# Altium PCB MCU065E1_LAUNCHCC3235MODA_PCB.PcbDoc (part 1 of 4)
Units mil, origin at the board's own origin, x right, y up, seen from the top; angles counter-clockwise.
Board outline 2300 x 4280 mil, 4 copper layers (TOP, GND, PWR, BOTTOM), stack 62 mil thick; 300 components, 199 nets, 970 pads, 475 vias.
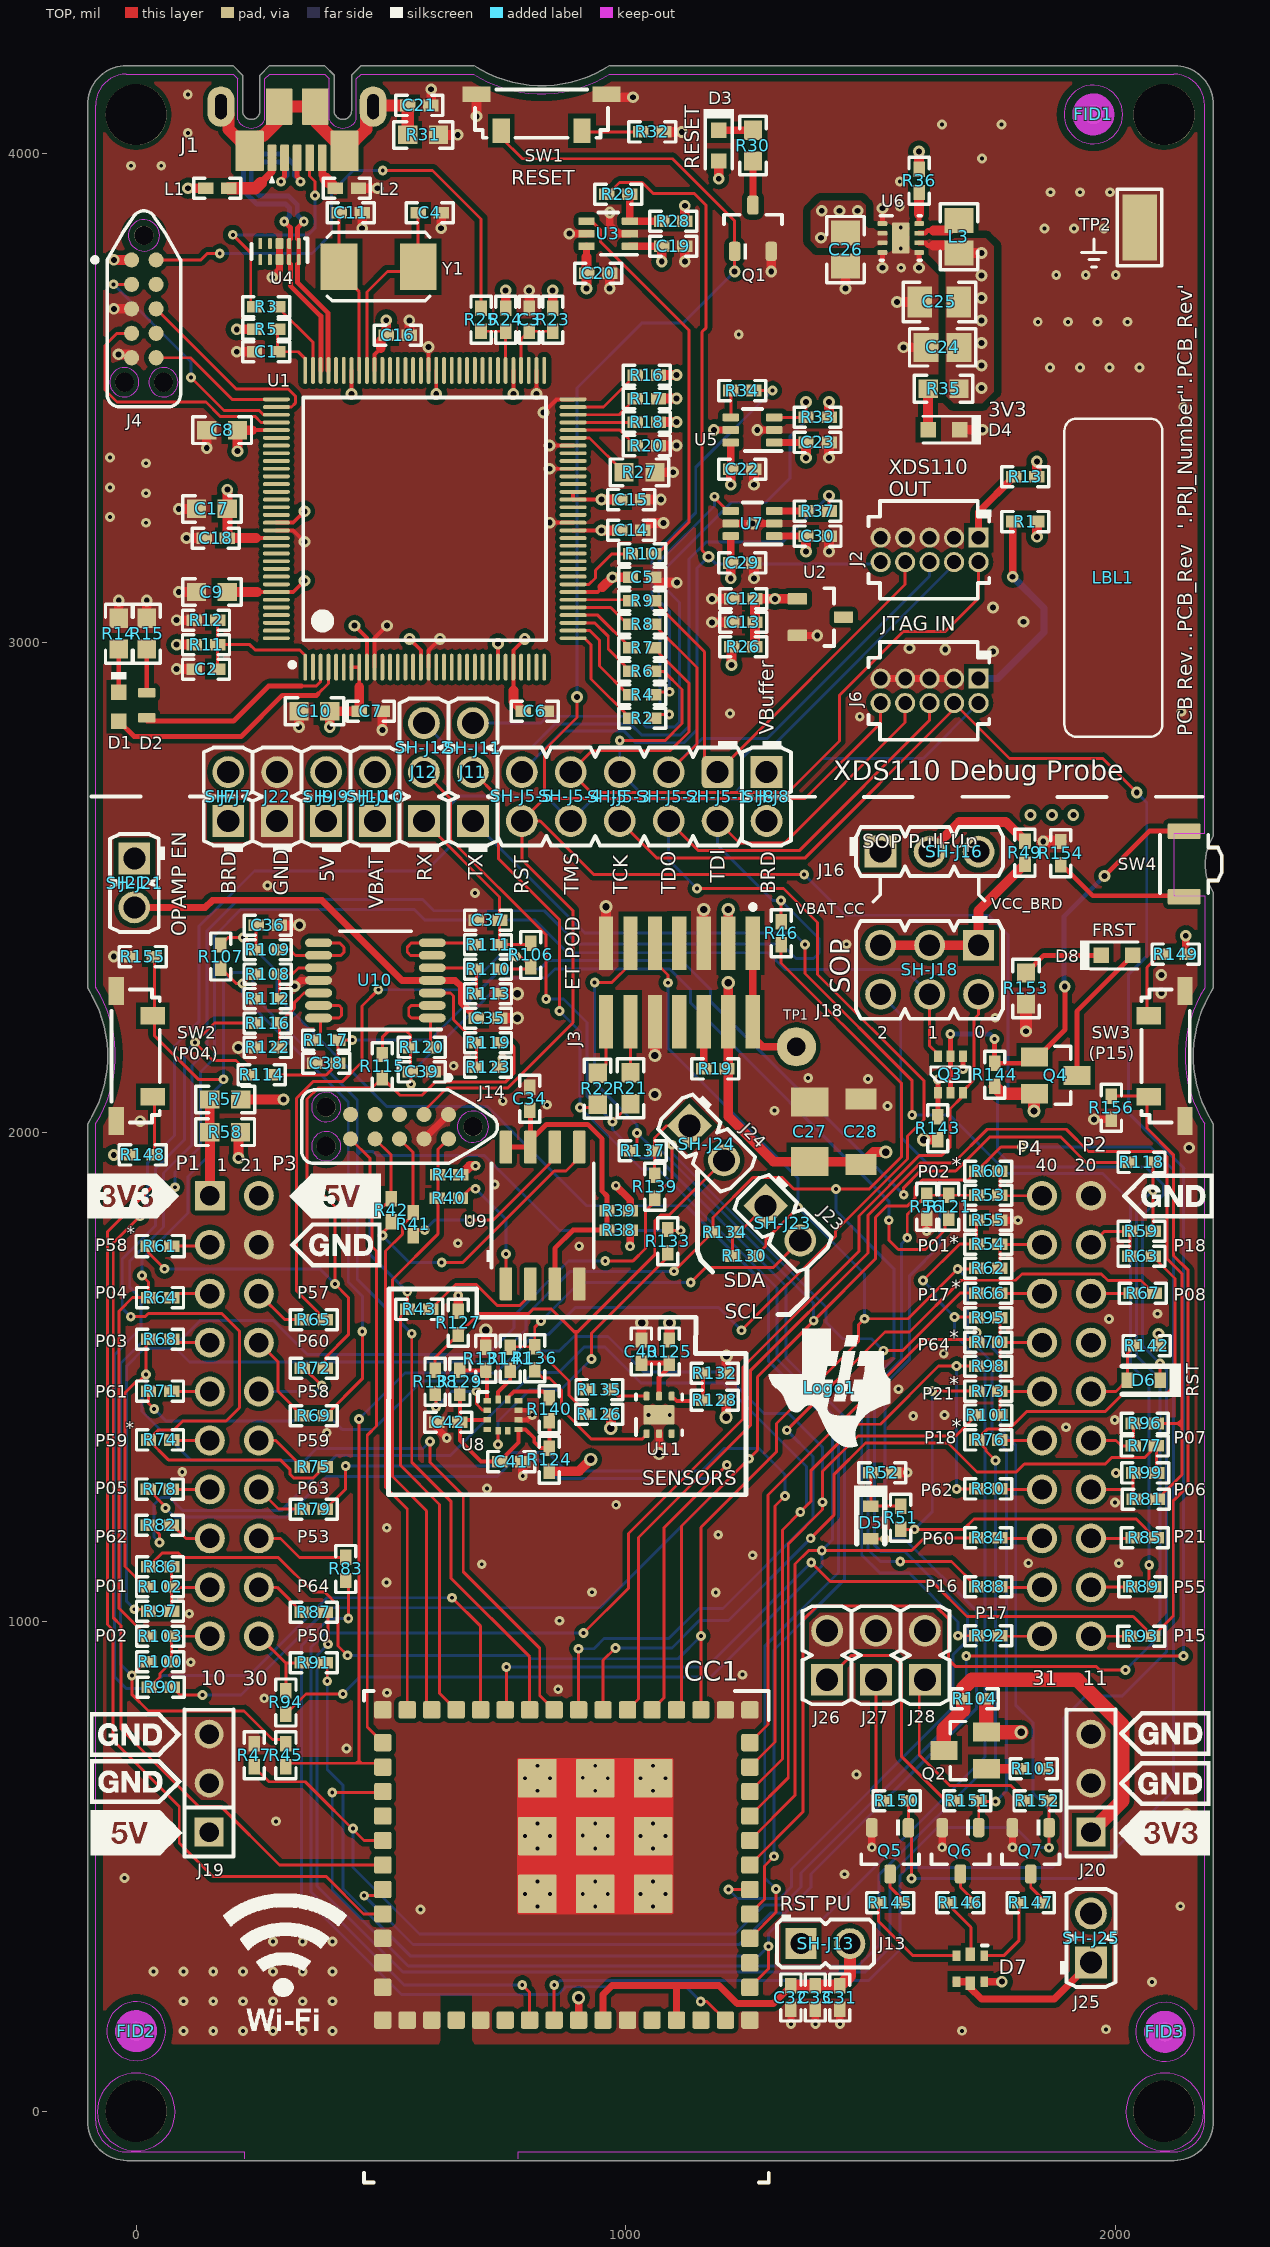
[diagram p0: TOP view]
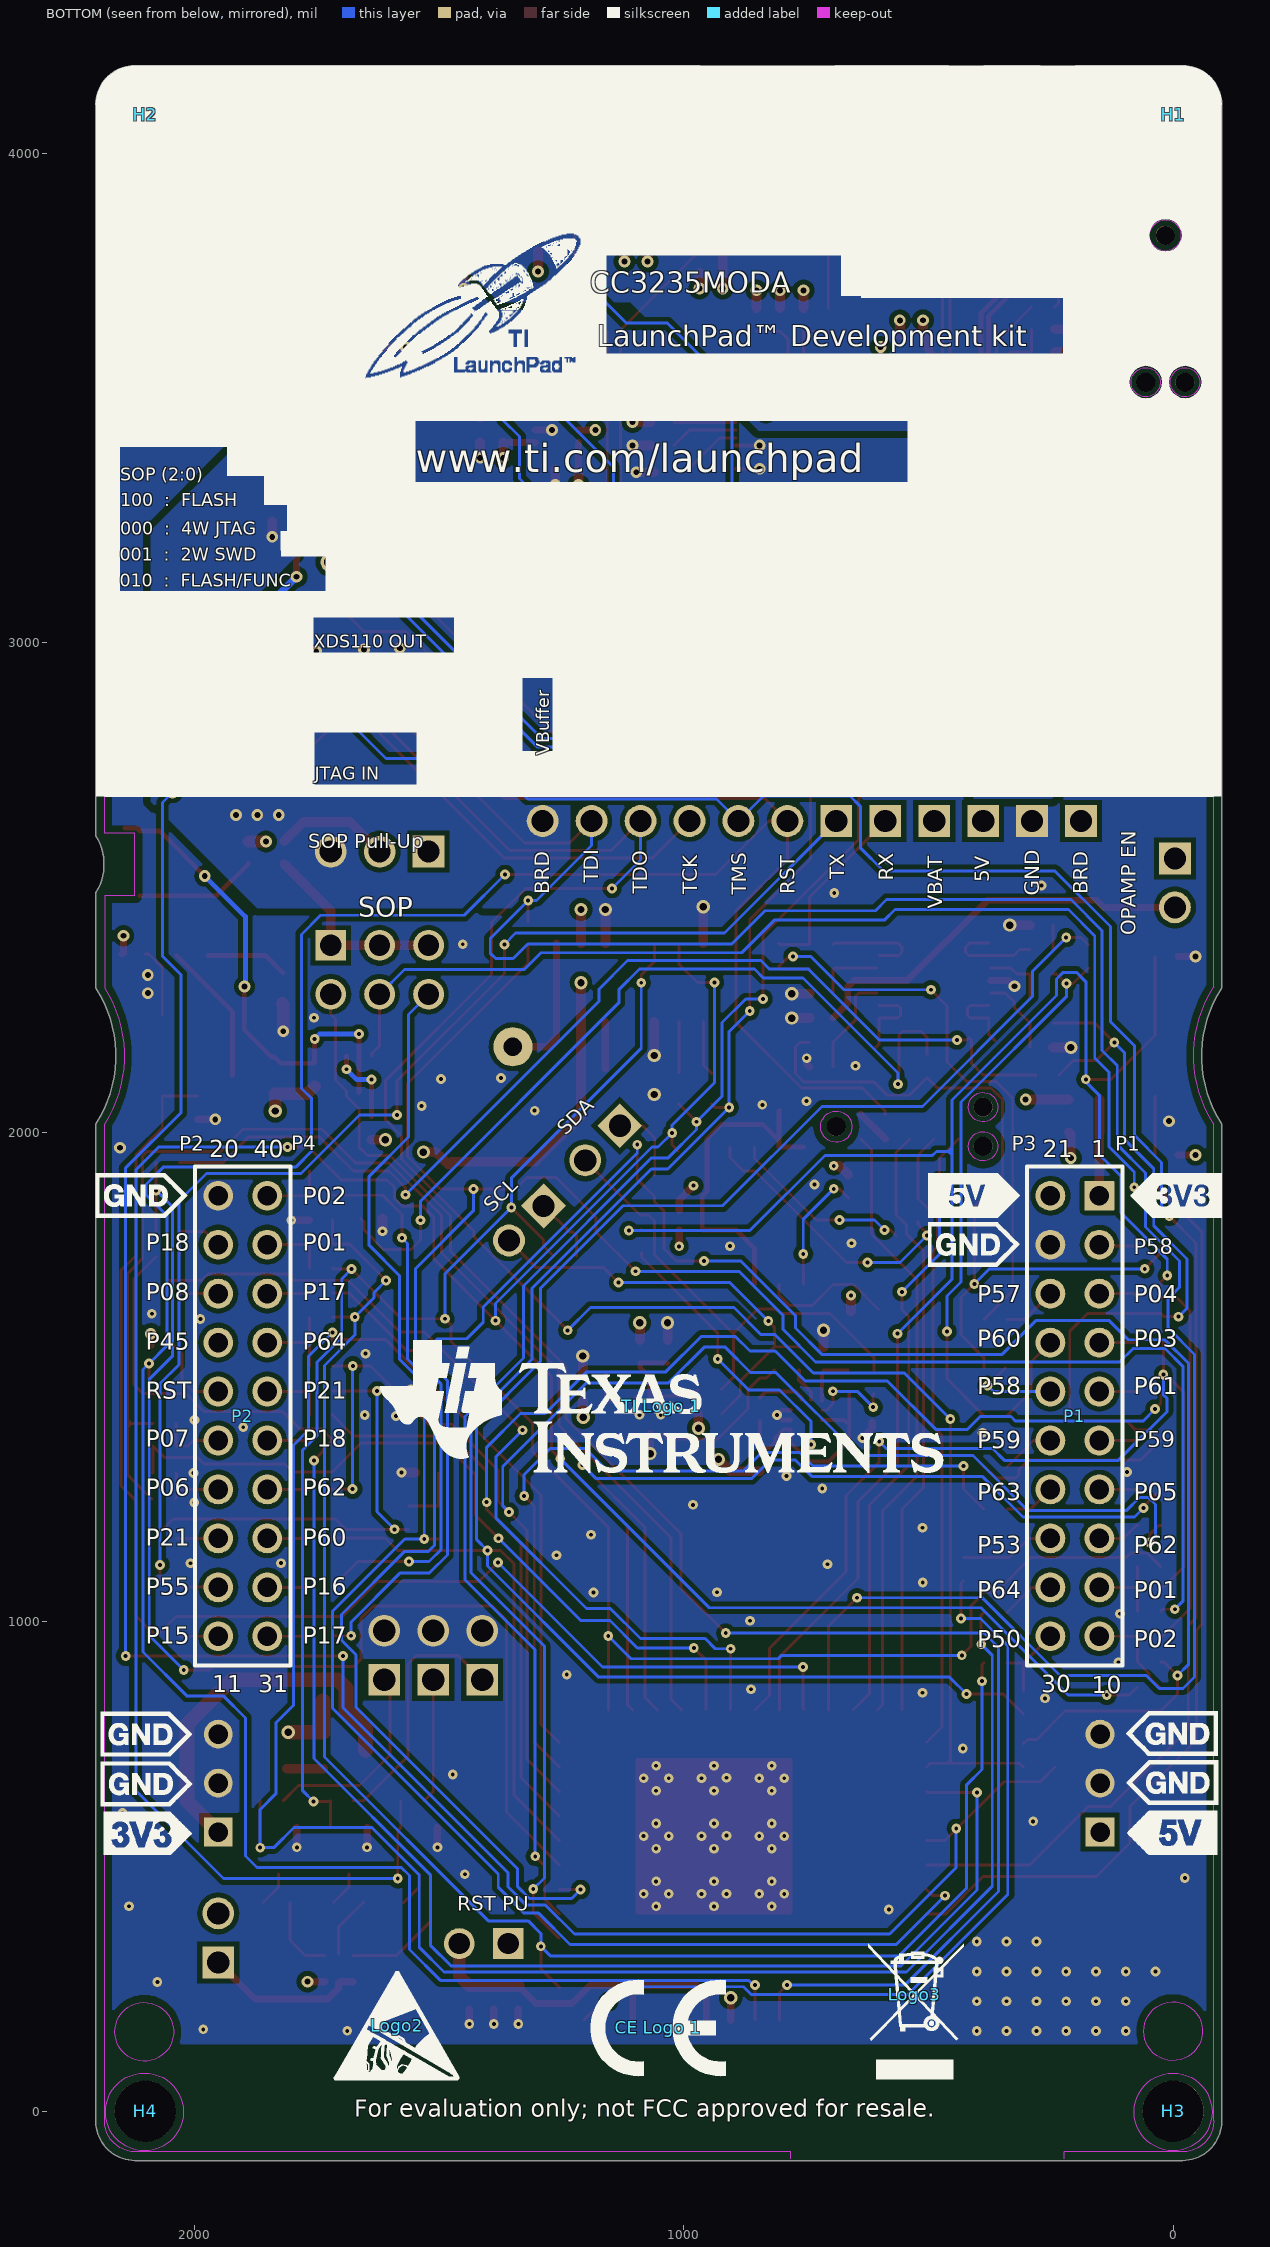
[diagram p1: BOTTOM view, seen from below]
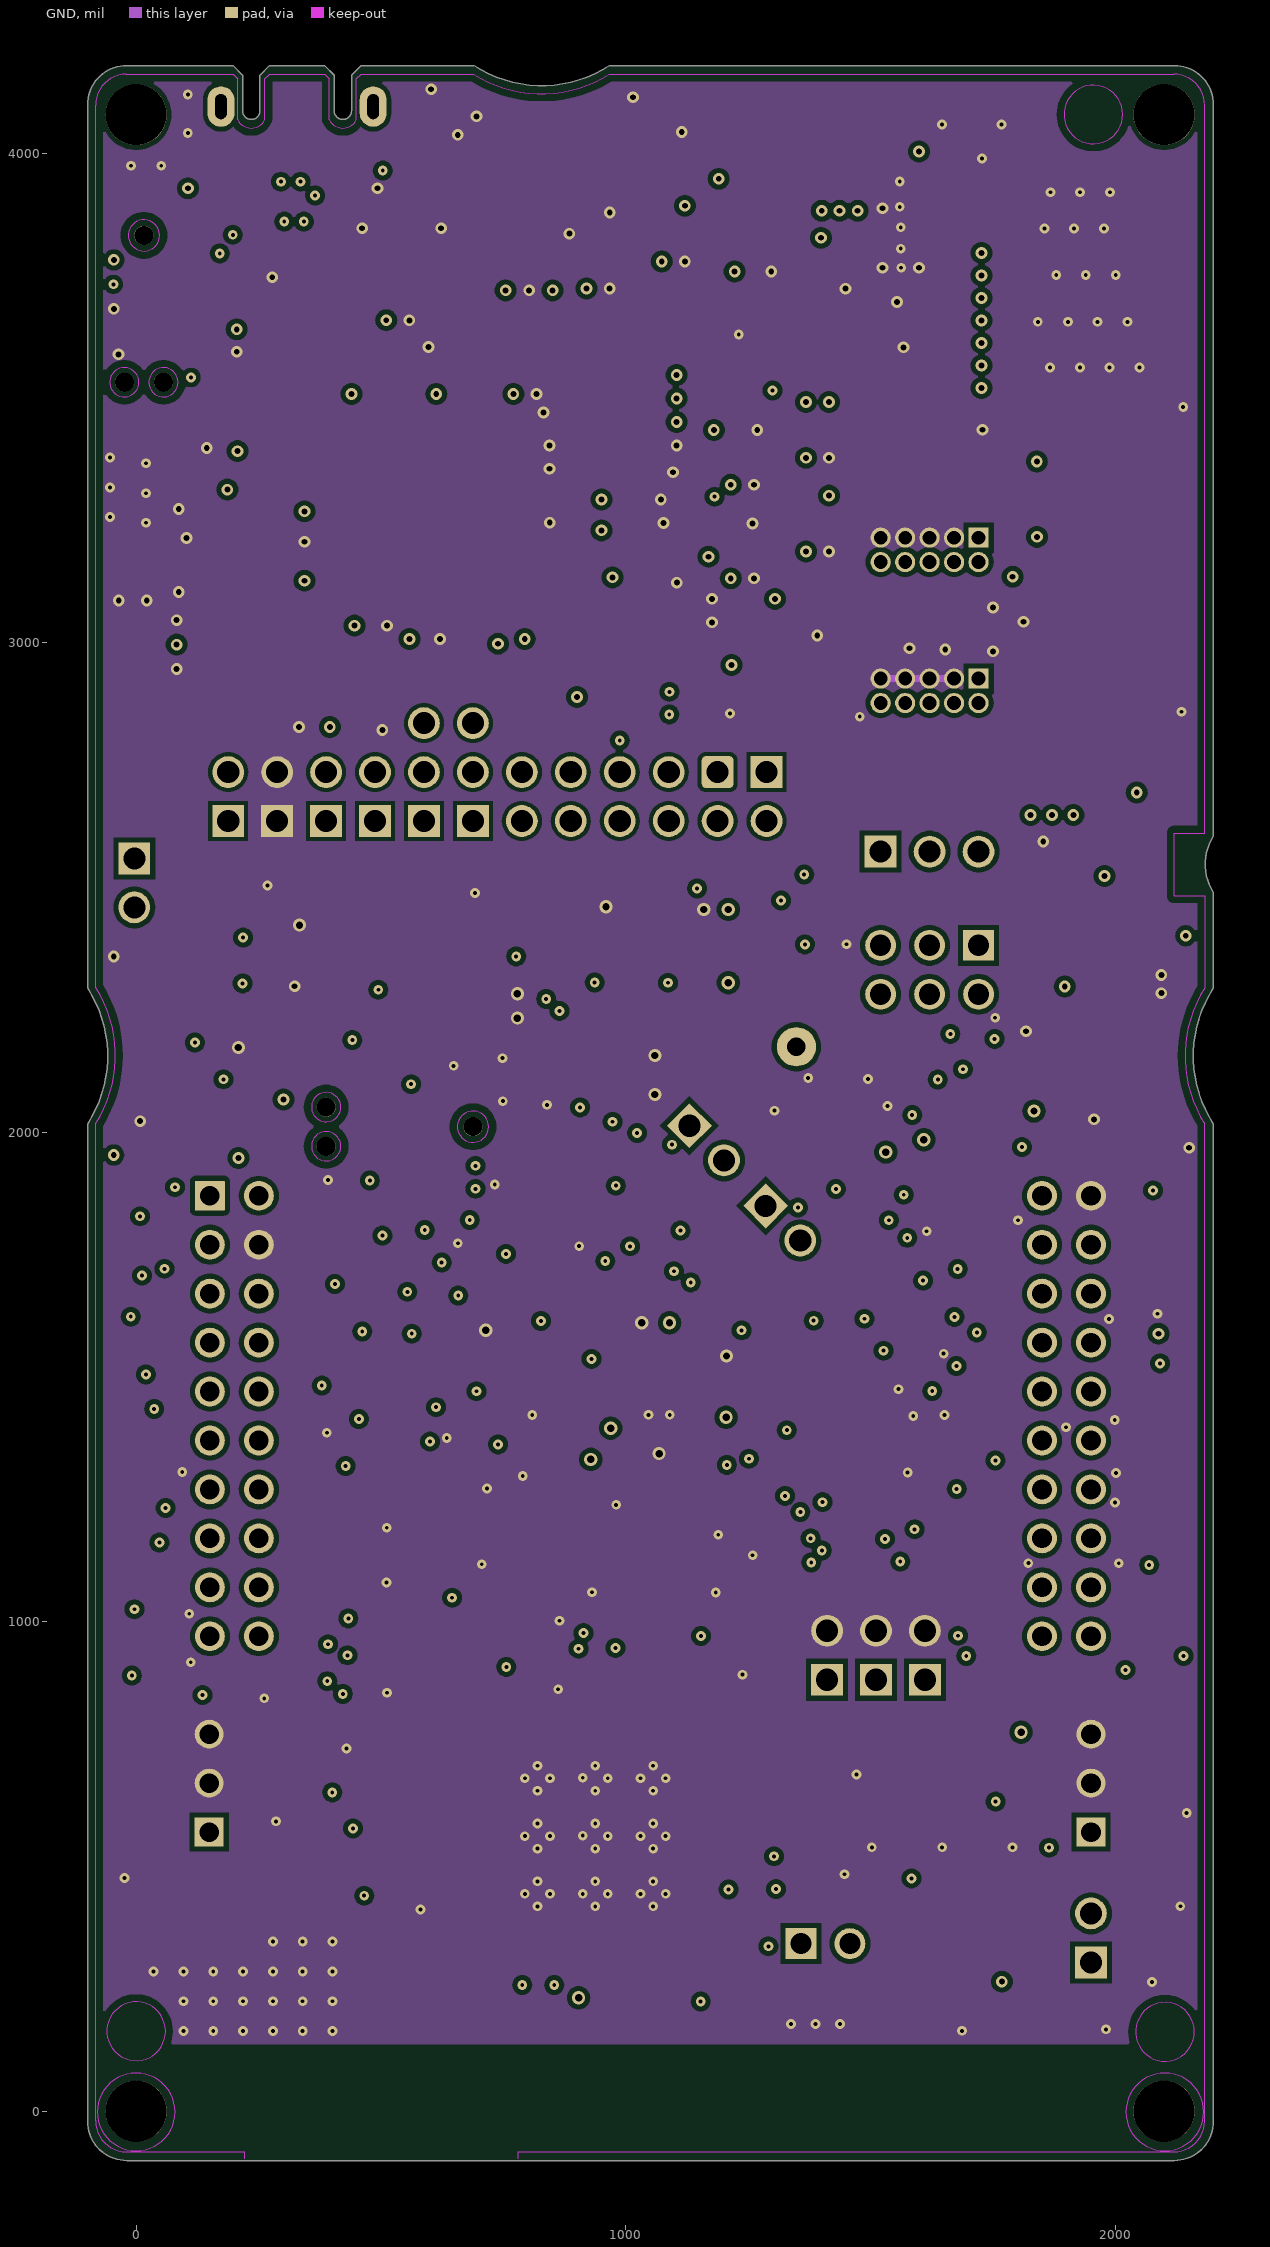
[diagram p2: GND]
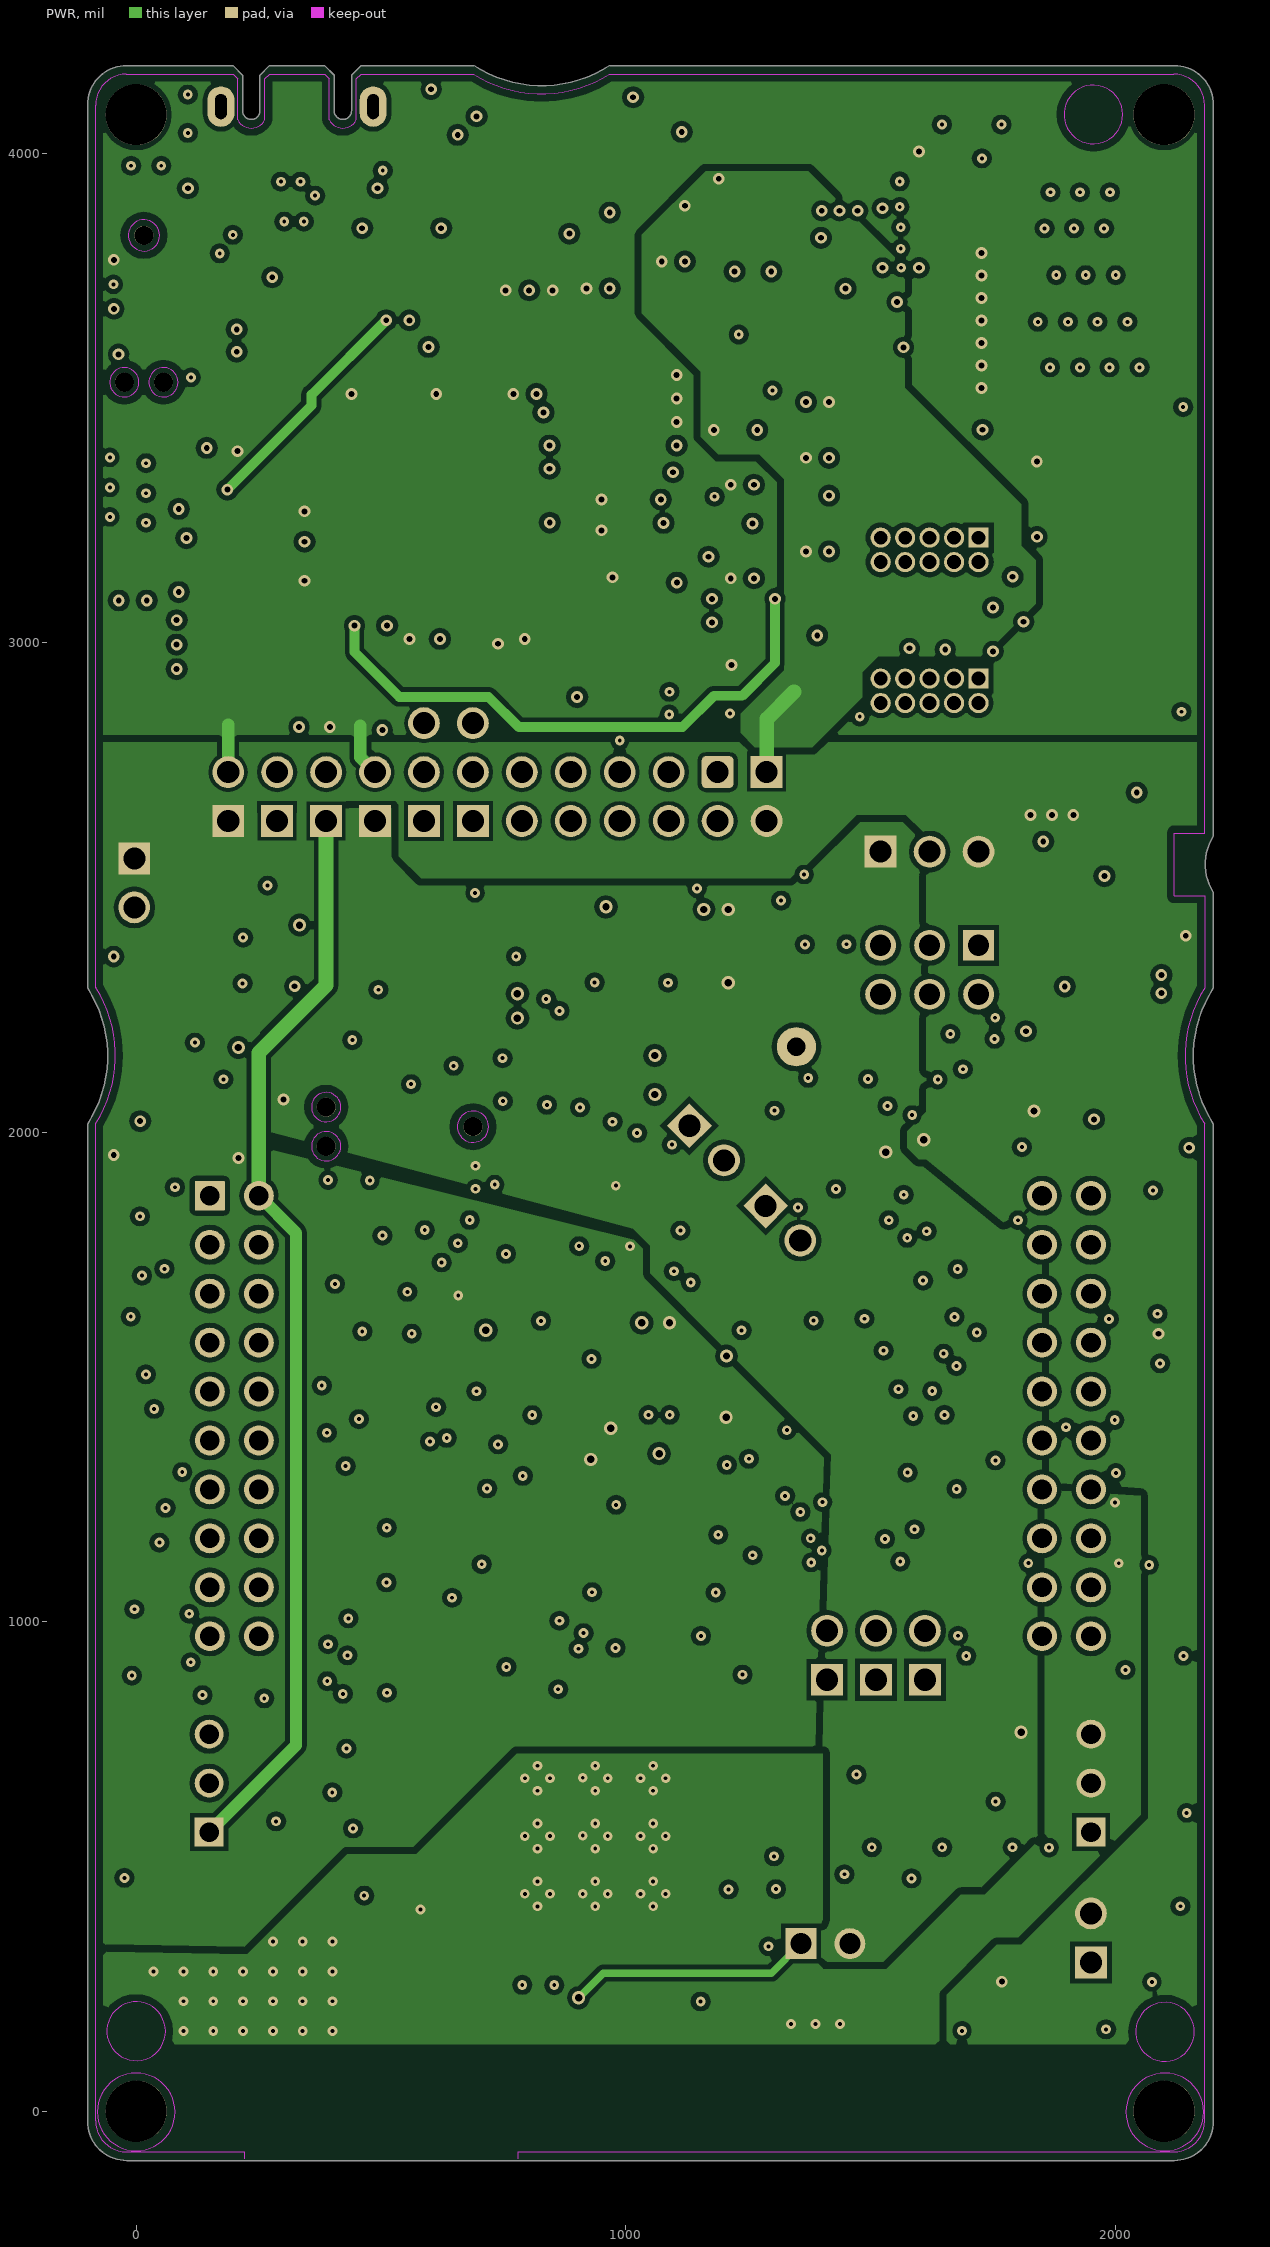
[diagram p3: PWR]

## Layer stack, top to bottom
Top Solder: solder mask 0.4, Solder Resist, Dk 3.5
TOP: signal copper 1.4
Dielectric1: core 16, FR-4 High Tg, Dk 4.5
GND: signal copper 0.6
Dielectric2: prepreg 26, FR-4 High Tg, Dk 4.5
PWR: signal copper 0.6
Dielectric3: core 16, FR-4 High Tg, Dk 4.5
BOTTOM: signal copper 1.4
Bottom Solder: solder mask 0.4, Solder Resist, Dk 3.5

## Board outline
-99.21,-20.74 -99.21,2017.26 ccw(c-312.46,2155.86) -99.21,2294.45 -99.21,4099.26 cw(c-19.21,4099.26) -19.21,4179.26 197.88,4179.26 217.57,4159.58 217.57,4086.74 ccw(c235.28,4086.74) 253,4086.74 253,4159.58 272.68,4179.26 384.89,4179.26 404.57,4159.58 404.57,4086.74 ccw(c422.29,4086.74) 440.01,4086.74 440.01,4159.58 459.69,4179.26 690.13,4179.26 ccw(c828.72,4392.51) 967.31,4179.26 2120.79,4179.26 cw(c2120.79,4099.26) 2200.79,4099.26 2200.7,2605 ccw(c2292.08,2547.43) 2200.72,2489.82 2200.79,2294.45 ccw(c2414.03,2155.86) 2200.79,2017.26 2200.79,-20.74 cw(c2120.79,-20.74) 2120.79,-100.74 -19.21,-100.74 cw(c-19.21,-20.74)

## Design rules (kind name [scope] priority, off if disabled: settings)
AssemblyTestPointUsage [All] p1: valid=2
Clearance Clearance_SW2KO [InComponent('SW4') and IsPad vs iskeepout and IsTrack] p1: gap=0 ignorepadtopadclearanceinfootprint=TRUE
Clearance Clearance_KO-Poly [IsKeepOut vs InPoly] p2: gap=15 ignorepadtopadclearanceinfootprint=TRUE
Clearance Clearance_Poly2HeaderPads [InPoly and (not (OnLayer('top') or OnLayer('bottom'))) vs InPadClass('HeaderPads')] p3: gap=8 ignorepadtopadclearanceinfootprint=TRUE
Clearance Clearance_SWITCH [(HasFootprint('SW_1188E') and IsPad) vs HasFootprint('SW_1188E') and IsPad] p4: gap=8 ignorepadtopadclearanceinfootprint=TRUE except(0: Arc-Hole Track-Hole SMDPad-Hole THPad-Hole Via-Hole Fill-Hole Poly-Hole Region-Hole Text-Hole)
Clearance Clearance_MH-KO [InPadClass('MH') vs IsKeepOut] p5: gap=0 ignorepadtopadclearanceinfootprint=TRUE
Clearance Clearance_KO-EDGE [InComponent('J1') and (IsPad or isfill) vs IsKeepOut] p6: gap=0 ignorepadtopadclearanceinfootprint=TRUE
Clearance Clearance_J3 [ispad and InComponent('J15') vs IsKeepOut and InComponent('J17')] p7: gap=0 ignorepadtopadclearanceinfootprint=TRUE
Clearance Clearance_FID [InComponentClass('FiducialMark') and IsPad vs IsKeepOut] p8: gap=0 ignorepadtopadclearanceinfootprint=TRUE
Clearance Clearance_SW [InPadClass('MH') vs InComponentClass('Switch')] p9: gap=8 ignorepadtopadclearanceinfootprint=TRUE
Clearance Clearance_Diff [InNet('XDSET_N') vs InNet('XDSET_P')] p10: gap=5 ignorepadtopadclearanceinfootprint=FALSE
Clearance Clearance_KO [iskeepout] p11: gap=5 ignorepadtopadclearanceinfootprint=FALSE except(0: Arc-Hole Track-Hole SMDPad-Hole THPad-Hole Via-Hole Fill-Hole Poly-Hole Region-Hole Text-Hole)
Clearance Clearance_TW-TW [IsTrack vs ALL AND NOT InPoly] p12: gap=6 ignorepadtopadclearanceinfootprint=TRUE
Clearance Clearance_MH [InPadClass('MH')] p13: gap=15 ignorepadtopadclearanceinfootprint=FALSE
Clearance "Clearance_50 ohm" [InNetClass('50 ohm') vs InPolygon] p14: gap=10 ignorepadtopadclearanceinfootprint=FALSE
Clearance Clearance_Poly_Poly [InPolygon vs InPolygon] p15: gap=15 ignorepadtopadclearanceinfootprint=FALSE
Clearance Clearance_Ploy_All [InPoly] p16: gap=10 ignorepadtopadclearanceinfootprint=FALSE
Clearance [All] p17: gap=8 ignorepadtopadclearanceinfootprint=TRUE except(0: Arc-Hole Track-Hole SMDPad-Hole THPad-Hole Via-Hole Fill-Hole Poly-Hole Region-Hole Text-Hole)
ComponentClearance ComponentClearance_Top&Bottom [InComponentClass('Top Side Components') vs InComponentClass('Bottom Side Components')] p1: gap=0 collisioncheckmode=3 verticalgap=0 showdistances=FALSE
ComponentClearance ComponentClearance_ShuntToShunt [InComponentClass('Shunt') vs InComponentClass('Shunt')] p2: gap=0 collisioncheckmode=3 verticalgap=0 showdistances=FALSE
ComponentClearance ComponentClearance_Shunt [InComponentClass('Header') vs InComponentClass('Shunt')] p3: gap=0 collisioncheckmode=3 verticalgap=0 showdistances=FALSE
ComponentClearance ComponentClearance_1 [InComponentClass('Overlap') vs InComponentClass('Overlap')] p4: gap=0 collisioncheckmode=3 verticalgap=0 showdistances=FALSE
ComponentClearance [All] p5: gap=10 collisioncheckmode=3 verticalgap=10 showdistances=FALSE
DiffPairsRouting [All] p1: maxlimit=10 minlimit=5 mostfreqgap=5 toplayer_minwidth=8 toplayer_maxwidth=15 toplayer_prefwidth=10 midlayer1_minwidth=8 midlayer1_maxwidth=15 midlayer1_prefwidth=10 midlayer2_minwidth=8 midlayer2_maxwidth=15 midlayer2_prefwidth=10 bottomlayer_minwidth=8 bottomlayer_maxwidth=15 bottomlayer_prefwidth=10 maxuncoupledlength=500
FabricationTestPointUsage [All] p1: valid=2 allowmultiple=FALSE
HoleSize [All] p1: absolutevalues=TRUE maxlimit=159 minlimit=6 maxpercent=80.000 minpercent=20.000
HoleToHoleClearance HoleToHoleClearance_Standoffs [InComponent('H1') OR     InComponent('H2')          OR     InComponent('H3')    OR     InComponent('H4') vs Hole] p1: gap=0 allowstackedmicrovias=TRUE
HoleToHoleClearance HoleToHoleClearance_1 [All] p2: gap=10 allowstackedmicrovias=TRUE
MinimumAnnularRing [IsVia] p1: minimumring=3
MinimumSolderMaskSliver [All] p1: minsoldermaskwidth=3.2
PlaneClearance [All] p1: clearance=8
PlaneConnect PlaneConnect_1 [All] p1: planeconnectstyle=Direct reliefexpansion=20 reliefentries=4 reliefconductorwidth=10 reliefairgap=10
PolygonConnect [All] p1: connectstyle=Direct reliefconductorwidth=15 reliefentries=4 polygonreliefangle="90 Angle" airgapwidth=10
RoomDefinition BOTTOMSILK [InComponentClass('Components Class 1')] p1: confinementstyle=ConfineIn formatcopy=TRUE lockcomponents=FALSE outline -120.62,4240.74 2220.44,4240.74 2220.44,2671.91 -120.62,2671.91
RoutingVias [All] p1: holewidth=8 width=24 viastyle="Through Hole" minholewidth=6 minwidth=12 maxholewidth=28 maxwidth=50 viatemplateguid#1={41FDFC50-AC36-4A40-A38E-85DC0862518D} viatemplateguid#2={7EB8106B-9EF6-4963-BEA4-F415A586DE84} viatemplateguid#3={4F6FB499-E6FF-4D0A-9C32-F9BF38F7A592} viatemplateguid#4={B3BBFEA9-3838-4BE5-98B3-281085A8F489} viatemplateguid#5={6AD91DA6-07A6-4121-AC78-2860BCF02B54} viatemplateguid#6={4AAE3504-B56D-40F2-9EA5-648483E9CB7A} viatemplateguid#7={CA1D6D1B-1EF2-42EE-B4B1-B4C514B9E4C3} viatemplateguid#8={597B6799-CFED-41C5-BE5F-4F951BC89095} viatemplateguid#9={4D60849D-32C0-4C25-877C-9BF03A911825} viatemplateguid#10={C3AF7BAA-7E46-44FA-8E17-6C0969281527} viatemplateguid#11={AE45BB74-DE73-46AB-B6E9-5F4A1C1AB101} viatemplatename#1=v50h20m0mx0 viatemplatename#2=v51h20m0mx0 viatemplatename#3=v51h30m0mx0 viatemplatename#4=v61h20m0mx0 viatemplatename#5=v61h25m0mx0 viatemplatename#6=v64h38m0mx0 viatemplatename#7=v76h38m0mx0 viatemplatename#8=v76h51m0mx0 viatemplatename#9=v102h51m0mx0 viatemplatename#10=v114h76m0mx0 viatemplatename#11=v127h71m0mx0
SilkToSilkClearance SilkToSilkClearance_BOTTOM [WithinRoom('BOTTOMSILK') and OnLayer('SILKSCREEN BOTTOM') and (isregion or IsText)] p1: silktosilkclearance=0
SilkToSilkClearance SilkToSilkClearance_pb-logo [(HasFootprint('Pb-Free_Overlay_Medium') OR HasFootprint('Pb-Free_Overlay_Small')) vs (HasFootprint('Pb-Free_Overlay_Medium') OR HasFootprint('Pb-Free_Overlay_Small'))] p2: silktosilkclearance=0
SilkToSilkClearance [All] p3: silktosilkclearance=3
SilkToSolderMaskClearance SilkToSolderMaskClearance_BottomSilk [IsPad and WithinRoom('BOTTOMSILK') vs OnLayer('SILKSCREEN BOTTOM') and WithinRoom('BOTTOMSILK')] p1: minsilkscreentomaskgap=0 clearancetoexposedcopper=TRUE
SilkToSolderMaskClearance [IsPad] p2: minsilkscreentomaskgap=2.49 clearancetoexposedcopper=FALSE
SilkToSolderMaskClearance SilkscreenOverComponentPads [IsPad] p3: minsilkscreentomaskgap=3 clearancetoexposedcopper=TRUE
SolderMaskExpansion SolderMaskExpansion_1 [InPadClass('MAsk')] p1: expansion=0.9
SolderMaskExpansion [All] p2: expansion=0
Width [All] p1: maxlimit=100 minlimit=6 preferedwidth=15 toplayer_prefwidth=6 midlayer1_prefwidth=10 midlayer2_minwidth=10 bottomlayer_prefwidth=6 minimp=50.000000 maximp=50.000000 favimp=50.000000
19 further rules are at their usual default settings.

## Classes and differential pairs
component class Shunt: SH-J5-1 SH-J5-2 SH-J5-3 SH-J5-4 SH-J5-5 SH-J7 SH-J8 SH-J9 SH-J10 SH-J11 SH-J12 SH-J13 SH-J16 SH-J18 SH-J21 SH-J23 SH-J24 SH-J25 SH-J26 SH-J27 SH-J28
pad class MH: J2-MH1 J2-MH2 J2-MH3 J28-MH1 J28-MH2 J28-MH3 SW1- SW2- SW3-MH1 SW3-MH2 SW4-
component class Label: LBL1
pad class MAsk: U1-1 U1-2 U1-3 U1-4 U1-5 U1-6 U1-7 U1-8 U1-9 U1-10 U1-11 U1-12 U1-13 U1-14 U1-15 U1-16 U1-17 U1-18 U1-19 U1-20 U1-21 U1-22 U1-23 U1-24 U1-25 U1-26 U1-27 U1-28 U1-29 U1-30 U1-31 U1-32 U1-33 U1-34 U1-35 U1-36 U1-37 U1-38 U1-39 U1-40 U1-41 U1-42 U1-43 U1-44 U1-45 U1-46 U1-47 U1-48 U1-49 U1-50 U1-51 U1-52 U1-53 U1-54 U1-55 U1-56 U1-57 U1-58 U1-59 U1-60 U1-61 U1-62 U1-63
pad class "direct connect": C7-2 C8-2 C10-2 C24-1 C25-1 C26-1 J10-1 J10-2 J19-1 J20-2 J21-2 J22-1 L1-2 R128-1 U1-55 U1-56 U1-57 U1-58 U1-59 U1-60 U1-61 U1-62 U1-63 U9-2 U9-3
component class FiducialMark: FID1 FID2 FID3
component class MCU065E1_EngineArea: C2 C3 C4 C7 C10 C31 C32 C33 C34 CC1 D5 J5 J13 J14 J16 J18 J26 L3 R38 R39 R40 R41 R42 R43 R44 R45 R46 R47 R49 R51 R52 R75 R76 R77 R78 R82 R83 R88 R122 U9
component class MCU065E1_LEDs_Switches_Sensors: C17 C18 C35 C40 C41 C42 D1 D6 D7 D8 J4 J11 J23 J24 J25 J26 J27 J28 Q1 Q3 Q4 Q5 Q6 Q7 R1 R3 R11 R13 R14 R16 R17 R22 R23 R26 R30 R33 R34 R43 R45 R55 R60 R72 R76 R93 R124 R125 R126 R127 R128 R129 R130 R131 R132 R133 R134 R135 R136 R137 R138 R139 R140 R141 R142 R143 R144 R145 R146 R147 R148 R149 R150 R151 R152 R153 R154 R155 R156 SW1 SW2 SW3 SW4 U5 U8 U11
component class MCU065E1_Host_Interface: C12 C13 C14 C35 C36 C37 C38 C39 J9 J19 J20 J21 J22 P1 P2 Q2 Q3 R1 R3 R17 R19 R22 R23 R24 R26 R53 R54 R55 R56 R57 R58 R59 R60 R61 R62 R63 R64 R65 R66 R67 R68 R69 R70 R71 R72 R73 R74 R75 R76 R77 R78 R79 R80 R81 R82 R83 R84 R85 R86 R87 R88 R89 R90 R91 R92 R93 R94 R95 R96 R97 R98 R99 R100 R101 R102 R103 R104 R105 R106 R107 R108 R109 R110 R111 R112 R113 R114 R115 R116 R117 R118 R119 R120 R121 R122 R123 R125 R128 R130 R132 R135 R136 R142 R145 R148 R150 R155 TP1 TP2 U10
component class MCU065E1_XDS110_Host: C1 C2 C3 C4 C5 C6 C7 C8 C9 C10 C11 C12 C13 C14 C15 C16 C17 C18 C31 C35 C39 C40 D1 D2 D6 J1 J2 J3 J4 J6 J13 J14 R1 R2 R3 R4 R5 R6 R7 R8 R9 R10 R11 R12 R13 R14 R15 R16 R17 R18 R19 R20 R21 R22 R23 R24 R25 R26 R27 R38 R43 R44 R45 R51 R55 R56 R60 R76 R93 R133 R135 TP1 U1 U2 Y1
component class AssemblyNote: ZZ1 ZZ2 ZZ3 ZZ4 ZZ5 ZZ6 ZZ7
component class MCU065E1_Hardware: "CE Logo 1" FID1 FID2 FID3 H1 H2 H3 H4 LBL1 Logo1 Logo2 Logo3 Logo4 SH-J5-1 SH-J5-2 SH-J5-3 SH-J5-4 SH-J5-5 SH-J7 SH-J8 SH-J9 SH-J10 SH-J11 SH-J12 SH-J13 SH-J16 SH-J18 SH-J21 SH-J23 SH-J24 SH-J25 SH-J26 SH-J27 SH-J28 "TI Logo 1" ZZ1 ZZ2 ZZ3 ZZ4 ZZ5 ZZ6 ZZ7
component class Header: J3 J4 J5 J7 J8 J9 J10 J11 J12 J13 J16 J18 J19 J20 J21 J22 J23 J24 J25 J26 J27 J28
component class Logo: Logo1 "TI Logo 1"
component class MCU065E1_XDS110_Circuit: C19 C20 C21 C22 C23 C24 C25 C26 C27 C28 C29 C30 D1 D3 D4 D8 J1 J5 J7 J8 J9 J10 J11 J12 J18 J19 J20 J22 J24 L1 L2 L3 Q1 R28 R29 R30 R31 R32 R33 R34 R35 R36 R37 R71 R72 SW1 U3 U4 U5 U6 U7 U11
pad class HeaderPads: J5-1 J5-2 J5-3 J5-4 J5-5 J5-6 J5-7 J5-8 J5-9 J5-10 J7-1 J7-2 J8-1 J8-2 J9-1 J9-2 J10-1 J10-2 J11-1 J11-2 J11-3 J12-1 J12-2 J12-3 J22-1 J22-2
component class Overlap: C38 C39 J5 J7 J8 J9 J10 J11 J12 J14 J22 J26 J27 J28 R44 R115 R123 U9
differential pair XDSET: +XDSET_P -XDSET_N

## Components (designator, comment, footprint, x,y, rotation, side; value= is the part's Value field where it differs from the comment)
C1 "LMK105BJ104KV-F" 0402 265.39,3594.58 r180 top locked value=0.1uF
C2 "CL05B103KO5NNNC" 0402 142.74,2946.17 r180 top locked value=0.01uF
C3 "EMK105BJ105KVHF" 0402 802.91,3660.02 r270 top locked value=1uF
C4 "CL05C220JB5NNNC" 0402 599.56,3878.32 r180 top locked value=22pF
C5 "CL05B103KO5NNNC" 0402 1033.57,3133.64 r0 top locked value=0.01uF
C6 "CL05B103KO5NNNC" 0402 814.28,2860.1 r0 top locked value=0.01uF
C7 "CL05B103KO5NNNC" 0402 479.32,2860.1 r0 top locked value=0.01uF
C8 "06033D104KAT2A" 0603 175.74,3434.35 r180 top locked value=0.1uF
C9 "06033D104KAT2A" 0603 154.87,3103.64 r180 top locked value=0.1uF
C10 "06033D104KAT2A" 0603 364.2,2860.1 r180 top locked value=0.1uF
C11 "CL05C220JB5NNNC" 0402 438.14,3878.32 r180 top locked value=22pF
C12 "CL05B103KO5NNNC" 0402 1240.69,3089.71 r180 top locked value=0.01uF
C13 "EMK105BJ105KVHF" 0402 1240.69,3041.71 r180 top locked value=1uF
C14 "CL05B103KO5NNNC" 0402 1011.33,3229.63 r0 top locked value=0.01uF
C15 "EMK105BJ105KVHF" 0402 1011.33,3292.62 r0 top locked value=1uF
C16 "C1005X5R1C225K050BC" 0402 534.56,3628.25 r0 top locked value=2.2uF
C17 "06033D104KAT2A" 0603 154.87,3273.49 r180 top locked value=0.1uF
C18 "EMK105BJ105KVHF" 0402 162.74,3213.88 r180 top locked value=1uF
C19 "GRM155R61A104KA01D" 0402 1097.38,3810.19 r0 top locked value=0.1uF
C20 "GRM155R61A104KA01D" 0402 943.8,3755.19 r0 top locked value=0.1uF
C21 "GRM155R71C103KA01D" 0402 578.55,4097.66 r0 top locked value=0.01uF
C22 "GRM155R61A104KA01D" 0402 1238.48,3354.19 r0 top locked value=0.1uF
C23 "GRM155R61A104KA01D" 0402 1392.07,3409.19 r0 top locked value=0.1uF
C24 "CMP-0008285-2" 0805 1647.53,3603.53 r180 top locked value=10uF
C25 "CMP-0007826-2" 0805_HV 1640.99,3696.23 r180 top locked value=22uF
C26 "CMP-0008285-2" 0805 1449.43,3803.3 r270 top locked value=10uF
C27 "CMP-0008934-2" 1206_180M 1376.59,2000.85 r90 top value=100uF
C28 "CMP-0008934-2" 1206_180 1480.59,2000.85 r90 top value=100uF
C29 "GRM155R61A104KA01D" 0402 1238.48,3163.01 r0 top locked value=0.1uF
C30 "GRM155R61A104KA01D" 0402 1392.07,3218.01 r0 top locked value=0.1uF
C31 "GRM155R61A104KA01D" 0402 1437.75,232.27 r270 top value=0.1uF
C32 "GRM155R61A104KA01D" 0402 1337.75,232.27 r270 top value=0.1uF
C33 "GRM155R61A104KA01D" 0402 1387.75,232.27 r270 top value=0.1uF
C34 "GRM155R61A104KA01D" 0402 804.3,2068.58 r90 top locked value=0.1uF
C35 "GRM155R61A103KA01D" 0402 718.86,2233.14 r0 top locked value=0.01uF
C36 "GRM155R71C103KA01D" 0402 268.86,2423.14 r0 top locked value=0.01uF
C37 "GRM155R71C103KA01D" 0402 718.86,2433.14 r180 top locked value=0.01uF
C38 "GRM155R71C103KA01D" 0402 388.67,2141.25 r180 top locked value=0.01uF
C39 "GRM155R71C103KA01D" 0402 583.86,2123.14 r0 top locked value=0.01uF
C40 "GRM155R61A104KA01D" 0402 1032.39,1552 r90 top locked value=0.1uF
C41 "GRM155R61A104KA01D" 0402 766.29,1327.19 r0 top locked value=0.1uF
C42 "GRM155R61A104KA01D" 0402 637.9,1407.38 r180 top locked value=0.1uF
CC1 "CC3235MODASM2MONR" MON0063A 878.9,356.38 r270 top
"CE Logo 1" "CE Mark" CE_Mark_5mm 1052.19,170.07 r180 bottom
D1 "SML-LX0603GW-TR" LED_SML-LX0603GW -35.48,2869.36 r90 top locked value=Green
D2 "19-217/R6C-AL1M2VY/3T" 19-217_R6C-AL1M2VY_3T_Red 21.67,2872.31 r90 top value=Red
D3 "CMP-0002892-2" WL-SMCW_YELLOW 1190.14,4015.76 r270 top locked value=Yellow
D4 "CMP-0002871-1" SML-31_Red 1650.48,3435.27 r180 top locked value=Red
D5 "CDBU00340" SOD-523F 1500.95,1202.57 r270 top value=45V
D6 "CDBU00340" SOD-523F 2058.46,1493.18 r180 top locked value=45V
D7 "19-337/R6GHBHC-A01/2T" 19-337_RGB 1704.35,291.19 r270 top value=RGB
D8 "CMP-0002871-1" SML-31_Red 2003.8,2361.41 r0 top locked value=Red
FID1 "CMP-0077181-1" Fiducial10-20 1955.64,4079.33 r90 top
FID2 "CMP-0077181-1" Fiducial10-20 0,163.48 r90 top
FID3 "CMP-0077181-1" Fiducial10-20 2101.9,162.18 r90 top
H1 "MAE-10" KY_MAE-10 0,4079 r180 bottom
H2 "MAE-10" KY_MAE-10 2100,4079 r180 bottom
H3 "MAE-10" KY_MAE-10 0,0 r180 bottom
H4 "MAE-10" KY_MAE-10 2100,0 r180 bottom
J1 "1051640001" Molex_1051640001 328.79,4152.47 r180 top
J2 "CMP-0075533-1" Samtec_FTSH-105-01-x-D-K 1621,3189.86 r270 top locked
J3 "CMP-0055564-1" Samtec_FTSH-107-01-x-DV 1109.79,2305.95 r270 top locked
J4 "CMP-0075101-1" Tag_TC2050-NL 15.79,3682.26 r0 top
J5 "61301021121" WURTH_61301021121 988,2685.86 r180 top locked
J6 "CMP-0075533-1" Samtec_FTSH-105-01-x-D-K 1621,2901.86 r270 top locked
J7 "CMP-0054794-1" WURTH_61300211121 188,2685.86 r90 top locked
J8 "CMP-0054794-1" WURTH_61300211121 1288,2685.86 r270 top locked
J9 "CMP-0054794-1" WURTH_61300211121 388,2685.86 r90 top locked
J10 "CMP-0054794-1" WURTH_61300211121 488,2685.86 r90 top locked
J11 "61300311121" WURTH_61300311121 688,2735.86 r90 top locked
J12 "61300311121" WURTH_61300311121 588,2735.86 r90 top locked
J13 "961102-6404-AR" 3M_961102-6404-AR 1408.24,342.43 r0 top locked
J14 "TC2050-IDC-NL-FP" Tag_TC2050-NL 538.2,2011.38 r270 top locked
J16 "CMP-0054796-1" WURTH_61300311121 1621,2573.25 r0 top
J18 "61300621121" Wurth_61300621121 1621,2331.86 r270 top locked
J19 "PEC03SAAN" CONN_PEC03SAAN 149.2,670.26 r90 top locked
J20 "PEC03SAAN" CONN_PEC03SAAN 1950.7,670.26 r90 top locked
J21 "CMP-0054794-1" WURTH_61300211121 -3.7,2509.28 r270 top locked
J22 "61300211121" WURTH_61300211121 288,2685.86 r90 top locked
J23 "61300211121" WURTH_61300211121 1321.4,1814.18 r315 top locked
J24 "61300211121" WURTH_61300211121 1165.6,1977.88 r315 top locked
J25 "CMP-0054794-1" WURTH_61300211121 1950.7,354 r90 top locked
J26 "61300211121" WURTH_61300211121 1411.5,931.5 r90 top locked
J27 "61300211121" WURTH_61300211121 1511.5,931.5 r90 top locked
J28 "61300211121" WURTH_61300211121 1611.5,931.5 r90 top locked
L1 "BLM15AG100SN1D" 0402 165.68,3928.5 r180 top locked value="10 ohm"
L2 "BLM15AG100SN1D" 0402 430.63,3928.5 r0 top locked value="10 ohm"
L3 "CMP-0059580-1" 0805 1680.99,3829.62 r270 top locked value=2.2uH
LBL1 "Size: 0.65\" x 0.20 \"" Label_650x200 1996.45,3133.05 r90 top
Logo1 "Texas Instruments" TI_Symbol_Overlay_Medium 1416.53,1477.98 r0 top
Logo2 "ESD Susceptible" ESD_Overlay_Medium 1585.52,174.23 r180 bottom
Logo3 "WEEE" WEEE_Minimum 527.54,237.97 r180 bottom
Logo4 "FCC disclaimer" FCC_disclaimer 2185.5,7507.55 r180 bottom locked
P1 "SSQ-110-03-T-D" BoosterPack_40pin_J1J3 200.7,1420.26 r180 bottom locked
P2 "SSQ-110-03-T-D" BoosterPack_40pin_J2J4 1900.7,1420.26 r180 bottom locked
Q1 "BSS138" SOT-23 1260.14,3847.02 r90 top locked value=50V
Q2 "FDN358P" SSOT-3 1693.52,737.12 r90 top locked value=-30V
Q3 "BSS84DW-7-F" SOT-363 1663.37,2118.12 r90 top locked value=-50V
Q4 "FDN358P" SSOT-3 1878.61,2116.1 r270 top locked value=-30V
Q5 "BSS138" SOT-23 1540.43,531.98 r270 top locked value=50V
Q6 "BSS138" SOT-23 1684.05,531.98 r270 top locked value=50V
Q7 "BSS138" SOT-23 1827.68,531.98 r270 top locked value=50V
R1 "CMP-0026852-3" 0402 1816.72,3247.73 r180 top locked value=1.0k
R2 "ERJ-2RKF33R0X" 0402 1033.57,2845.64 r180 top locked value=33.0
R3 "ERJ-2GE0R00X" 0402 265.39,3686.18 r180 top locked value=0
R4 "ERJ-2RKF33R0X" 0402 1033.57,2893.64 r180 top locked value=33.0
R5 "CRCW0402100RJNED" 0402 265.39,3640.38 r180 top locked value=100
R6 "ERJ-2RKF33R0X" 0402 1033.57,2941.64 r180 top locked value=33.0
R7 "ERJ-2RKF33R0X" 0402 1033.57,2989.64 r180 top locked value=33.0
R8 "ERJ-2RKF33R0X" 0402 1033.57,3037.64 r180 top locked value=33.0
R9 "ERJ-2RKF33R0X" 0402 1033.57,3085.64 r180 top locked value=33.0
R10 "ERJ-2RKF33R0X" 0402 1033.57,3181.64 r180 top locked value=33.0
R11 "CRCW0402330KJNED" 0402 142.74,2996.17 r180 top locked value=330k
R12 "CRCW0402220KJNED" 0402 142.74,3046.17 r0 top locked value=220k
R13 "CMP-0026852-3" 0402 1816.46,3338.87 r180 top locked value=1.0k
R14 "CRCW0603220RJNEA" 0603 -35.48,3018.53 r270 top locked value=220
R15 "CRCW0603220RJNEA" 0603 21.67,3018.53 r270 top locked value=220
R16 "CRCW04021K00JNED" 0402 1043.57,3546.89 r0 top locked value=1.0k
R17 "CRCW04021K00JNED" 0402 1043.57,3498.89 r0 top locked value=1.0k
R18 "CRCW04021K00JNED" 0402 1043.57,3450.89 r0 top locked value=1.0k
R19 "CMP-0026852-3" 0402 1183.41,2129.33 r0 top locked value=1.0k
R20 "CRCW04021K00JNED" 0402 1043.57,3402.89 r0 top locked value=1.0k
R21 "CMP-0025787-4" 0603 1009.79,2089.95 r90 top locked value=33
R22 "CMP-0025787-4" 0603 942.79,2088.95 r90 top locked value=33
R23 "CRCW040251R0JNED" 0402 850.91,3660.02 r270 top locked value=51
R24 "CRCW040210K0JNED" 0402 754.91,3660.02 r90 top locked value=10k
R25 "CRCW0402100RFKED" 0402 704.56,3660.02 r270 top locked value=100
R26 "CRCW04021K00JNED" 0402 1240.11,2992.2 r180 top locked value=1.0k
R27 "CRCW06034K87FKEA" 0603 1028.31,3348.25 r180 top locked value=4.87k
R28 "CRCW0402100KJNED" 0402 1097.38,3861.37 r0 top locked value=100k
R29 "CRCW040210K0JNED" 0402 985.14,3916.37 r0 top locked value=10k
R30 "CMP-0025765-4" 0603 1260.14,4015.76 r90 top locked value=270
R31 "CRCW0603100KJNEAC" 0603 586.43,4037.66 r180 top locked value=100k
R32 "CMP-0026656-1" 0402 1054.6,4043.62 r180 top locked value=100
R33 "CRCW0402100KJNED" 0402 1392.07,3460.37 r0 top locked value=100k
R34 "ERJ-2RKF33R0X" 0402 1238.48,3515.37 r0 top locked value=33.0
R35 "CMP-0025765-4" 0603 1649.49,3519.06 r180 top locked value=270
R36 "CMP-0026823-3" 0402 1599.51,3943.5 r90 top locked value=100k
R37 "ERJ-2RKF33R0X" 0402 1392.07,3269.19 r180 top locked value=33.0
R38 "ERJ-2GE0R00X" 0402 985.5,1800.18 r0 top locked value=0
R39 "ERJ-2GE0R00X" 0402 985.5,1839.98 r0 top locked value=0
R40 "ERJ-2GE0R00X" 0402 639.03,1865.18 r0 top locked value=0
R41 "ERJ-2GE0R00X" 0402 565.94,1812.42 r270 top locked value=0
R42 "ERJ-2GE0R00X" 0402 521.02,1840.8 r270 top locked value=0
R43 "ERJ-2GE0R00X" 0402 578,1638 r0 top locked value=0
R44 "CRCW0402100KDHEDP" 0402 639.93,1913.28 r180 top locked value=100k
R45 "ERJ-2GE0R00X" 0402 306,727 r270 top locked value=0
R46 "ERJ-2GE0R00X" 0402 1317.6,2406.48 r90 top locked value=0
R47 "CRCW0402100KJNED" 0402 241,727 r270 top locked value=100k
R49 "CRCW040210K0JNED" 0402 1815.91,2571.22 r90 top locked value=10k
R51 "CRCW04022K20JNED" 0402 1561.65,1212.41 r270 top value=2.2k
R52 "CRCW040210K0JNED" 0402 1524.57,1304.23 r180 top value=10k
R53 "RC0402JR-070RL" 0402 1740.79,1871.27 r0 top locked value=0
R54 "RC0402JR-070RL" 0402 1740.79,1771.27 r0 top locked value=0
R55 "CMP-0026823-3" 0402 1740.79,1820.27 r0 top locked value=100k
R56 "CMP-0026823-3" 0402 1615,1847.65 r270 top locked value=100k
R57 "CMP-0025874-3" 0603 182.08,2066.92 r180 top locked value=0
R58 "CMP-0025874-3" 0603 181.86,2000.15 r180 top locked value=0
R59 "RC0402JR-070RL" 0402 2053.93,1797.42 r0 top locked value=0
R60 "RC0402JR-070RL" 0402 1740.79,1920.27 r0 top locked value=0
R61 "RC0402JR-070RL" 0402 48.7,1767.51 r0 top value=0
R62 "RC0402JR-070RL" 0402 1740.79,1722.27 r0 top locked value=0
R63 "RC0402JR-070RL" 0402 2053.9,1746.34 r0 top locked value=0
R64 "RC0402JR-070RL" 0402 48.79,1662.26 r0 top locked value=0
R65 "RC0402JR-070RL" 0402 363,1617 r0 top locked value=0
R66 "RC0402JR-070RL" 0402 1740.79,1671.27 r0 top locked value=0
R67 "RC0402JR-070RL" 0402 2056.87,1671.27 r0 top locked value=0
R68 "RC0402JR-070RL" 0402 48.79,1577.26 r0 top locked value=0
R69 "RC0402JR-070RL" 0402 363,1421 r0 top locked value=0
R70 "RC0402JR-070RL" 0402 1740.79,1571.27 r0 top locked value=0
R71 "RC0402JR-070RL" 0402 48.79,1471.26 r0 top locked value=0
R72 "RC0402JR-070RL" 0402 363,1518 r0 top locked value=0
R73 "RC0402JR-070RL" 0402 1740.79,1471.27 r0 top locked value=0
R74 "RC0402JR-070RL" 0402 48.79,1371.26 r0 top locked value=0
R75 "RC0402JR-070RL" 0402 363,1316.14 r0 top locked value=0
R76 "RC0402JR-070RL" 0402 1740.79,1371.27 r0 top locked value=0
R77 "RC0402JR-070RL" 0402 2060.79,1359.09 r0 top locked value=0
R78 "RC0402JR-070RL" 0402 48,1271 r0 top locked value=0
R79 "RC0402JR-070RL" 0402 363,1230 r0 top locked value=0
R80 "RC0402JR-070RL" 0402 1740.79,1271.27 r0 top locked value=0
R81 "RC0402JR-070RL" 0402 2062.8,1250.48 r0 top locked value=0
R82 "RC0402JR-070RL" 0402 48,1197 r0 top locked value=0
R83 "RC0402JR-070RL" 0402 428,1107.76 r270 top locked value=0
R84 "RC0402JR-070RL" 0402 1740.79,1171.27 r0 top locked value=0
R85 "RC0402JR-070RL" 0402 2060.79,1171.27 r0 top locked value=0
R86 "RC0402JR-070RL" 0402 48.79,1112.26 r0 top locked value=0
R87 "RC0402JR-070RL" 0402 363,1019 r0 top locked value=0
R88 "RC0402JR-070RL" 0402 1740.79,1071.27 r0 top locked value=0
R89 "RC0402JR-070RL" 0402 2055.79,1071.27 r0 top locked value=0
R90 "RC0402JR-070RL" 0402 50,866 r180 top locked value=0
R91 "RC0402JR-070RL" 0402 363,916 r0 top locked value=0
R92 "RC0402JR-070RL" 0402 1740.79,971.27 r0 top locked value=0
R93 "RC0402JR-070RL" 0402 2053.79,970.26 r0 top locked value=0
R94 "RC0402JR-070RL" 0402 306,835 r270 top locked value=0
R95 "RC0402JR-070RL" 0402 1740.79,1621.27 r0 top locked value=0
R96 "RC0402JR-070RL" 0402 2060.79,1404.97 r0 top locked value=0
R97 "RC0402JR-070RL" 0402 48.79,1021.26 r0 top locked value=0
R98 "RC0402JR-070RL" 0402 1740.79,1522.27 r0 top locked value=0
R99 "RC0402JR-070RL" 0402 2061.2,1303.88 r0 top locked value=0
R100 "RC0402JR-070RL" 0402 49,918 r0 top locked value=0
R101 "RC0402JR-070RL" 0402 1740.79,1422.27 r0 top locked value=0
R102 "RC0402JR-070RL" 0402 48.79,1071.26 r0 top locked value=0
R103 "RC0402JR-070RL" 0402 49,970 r0 top locked value=0
R104 "ERJ-2GE0R00X" 0402 1713.21,842.33 r0 top locked value=0
R105 "ERJ-2GE0R00X" 0402 1833.84,699.71 r0 top locked value=0
R106 "RC0402JR-070RL" 0402 805.86,2362.14 r90 top locked value=0
R107 "RC0402JR-070RL" 0402 173.06,2358.99 r90 top locked value=0
R108 "CRCW0402576KFKED" 0402 268.86,2323.14 r0 top locked value=576k
R109 "ERJ-2RKF4700X" 0402 268.86,2373.14 r180 top locked value=470
R110 "CRCW0402576KFKED" 0402 718.86,2333.14 r180 top locked value=576k
R111 "ERJ-2RKF4700X" 0402 718.86,2383.14 r0 top locked value=470
R112 "CRCW0402422KFKED" 0402 268.86,2273.14 r0 top locked value=422k
R113 "CRCW0402422KFKED" 0402 718.86,2283.14 r180 top locked value=422k
R114 "RC0402JR-070RL" 0402 256.86,2117.14 r0 top locked value=0
R115 "RC0402JR-070RL" 0402 502.86,2135.14 r90 top locked value=0
R116 "CRCW0402576KFKED" 0402 268.86,2223.14 r0 top locked value=576k
R117 "ERJ-2RKF4700X" 0402 387.86,2187.84 r0 top locked value=470
R118 "RC0402JR-070RL" 0402 2053.97,1938.27 r0 top locked value=0
R119 "CRCW0402576KFKED" 0402 718.86,2183.14 r180 top locked value=576k
R120 "ERJ-2RKF4700X" 0402 583.86,2173.14 r180 top locked value=470
R121 "RC0402JR-070RL" 0402 1660,1847.65 r90 top locked value=0
R122 "CRCW0402422KFKED" 0402 268.86,2173.14 r0 top locked value=422k
R123 "CRCW0402422KFKED" 0402 718.86,2133.14 r180 top locked value=422k
R124 "ERJ-2GE0R00X" 0402 844.29,1331.19 r90 top locked value=0
R125 "ERJ-2GE0R00X" 0402 1089.39,1552 r90 top locked value=0
R126 "CRCW04023K30JNED" 0402 946.29,1424.19 r0 top locked value=3.3k
R127 "CRCW04023K30JNED" 0402 658.02,1610.43 r90 top locked value=3.3k
R128 "ERJ-2GE0R00X" 0402 1182.01,1452.64 r0 top value=0
R129 "ERJ-2GE0R00X" 0402 661.52,1489.94 r270 top value=0
R130 "ERJ-2GE0R00X" 0402 1242.1,1747.18 r180 top value=0
R131 "ERJ-2GE0R00X" 0402 714.29,1537.19 r90 top locked value=0
R132 "ERJ-2GE0R00X" 0402 1182.01,1507.79 r180 top value=0
R133 "ERJ-2GE0R00X" 0402 1085.9,1777.68 r270 top locked value=0
R134 "ERJ-2GE0R00X" 0402 1202.4,1796.18 r0 top locked value=0
R135 "ERJ-2GE0R00X" 0402 946.55,1474.4 r180 top locked value=0
R136 "ERJ-2GE0R00X" 0402 814.29,1538.19 r90 top locked value=0
R137 "ERJ-2GE0R00X" 0402 1035.3,1962.08 r0 top locked value=0
R138 "ERJ-2GE0R00X" 0402 610.62,1489.94 r90 top value=0
R139 "ERJ-2GE0R00X" 0402 1059.3,1888.38 r90 top locked value=0
R140 "ERJ-2GE0R00X" 0402 844.29,1434.19 r270 top locked value=0
R141 "ERJ-2GE0R00X" 0402 764.29,1537.19 r90 top locked value=0
R142 "CRCW0402100KJNED" 0402 2064.83,1564.25 r0 top locked value=100k
R143 "CRCW040210K0JNED" 0402 1637.78,2008.3 r270 top locked value=10k
R144 "ERJ-2RKF1003X" 0402 1753.78,2117.26 r270 top locked value=100k
R145 "CRCW0402261RFKED" 0402 1540.43,426.22 r180 top locked value=261
R146 "CRCW0402309RFKED" 0402 1684.05,426.22 r180 top locked value=309
R147 "CRCW0402200RJNED" 0402 1827.68,426.22 r180 top locked value=200
R148 "CRCW04021K00JNED" 0402 13.54,1953.6 r180 top locked value=1.0k
R149 "CRCW04021K00JNED" 0402 2123.66,2364.02 r0 top locked value=1.0k
R150 "CRCW0402100KJNED" 0402 1554.21,634.22 r0 top locked value=100k
R151 "CRCW0402100KJNED" 0402 1697.83,634.22 r0 top locked value=100k
R152 "CRCW0402100KJNED" 0402 1841.45,634.22 r0 top locked value=100k
R153 "CRCW0603270RJNEA" 0603 1817.89,2293.66 r90 top locked value=270
R154 "CRCW04021K00JNED" 0402 1888.8,2570.35 r270 top locked value=1.0k
R155 "CRCW040210K0JNED" 0402 13.54,2358.95 r0 top locked value=10k
R156 "CRCW040210K0JNED" 0402 1992.54,2049.98 r90 top locked value=10k
SH-J5-1 "Place J5: 1-2" SNT-100-BK-G 1188.32,2685.09 r90 top value=1x2
SH-J5-2 "Place J5: 3-4" SNT-100-BK-G 1087.31,2685.63 r90 top value=1x2
SH-J5-3 "Place J5: 5-6" SNT-100-BK-G 987.25,2685.49 r90 top value=1x2
SH-J5-4 "Place J5: 7-8" SNT-100-BK-G 887.28,2686.15 r90 top value=1x2
SH-J5-5 "Place J5: 9-10" SNT-100-BK-G 787.92,2685.97 r90 top value=1x2
SH-J7 "Place J7: 2-3" SNT-100-BK-G 187.99,2685.87 r90 top value=1x2
SH-J8 "Place J8: 2-3" SNT-100-BK-G 1288.77,2685.21 r90 top value=1x2
SH-J9 "Place J9: 1-2" SNT-100-BK-G 387.99,2685.87 r90 top value=1x2
SH-J10 "Place J10: 1-2" SNT-100-BK-G 487.99,2685.87 r90 top value=1x2
SH-J11 "Place J11: 2-3" SNT-100-BK-G 688.18,2784.66 r90 top value=1x2
SH-J12 "Place J12: 2-3" SNT-100-BK-G 587.75,2785.34 r90 top value=1x2
SH-J13 "Place J13: 1-2" SNT-100-BK-G 1409.03,342.43 r180 top value=1x2
SH-J16 "Place J16: 2-3" SNT-100-BK-G 1671.79,2572.93 r180 top value=1x2
SH-J18 "Place J18: 3-4" SNT-100-BK-G 1621.5,2332.03 r90 top value=1x2
SH-J21 "Place J21: 1-2" SNT-100-BK-G -3.25,2508.7 r90 top value=1x2
SH-J23 "Place J23: 1-2" SNT-100-BK-G 1320.7,1813.87 r135 top value=1x2
SH-J24 "Place J24: 1-2" SNT-100-BK-G 1166.12,1975.86 r135 top value=1x2
SH-J25 "Place J25: 1-2" SNT-100-BK-G 1951.36,353.46 r90 top value=1x2
SW1 "TL3330AF260QG" SW_TL3330 828.3,4080.84 r180 top
SW2 "TL3330AF260QG" SW_TL3330 -1.05,2155.53 r270 top
SW3 "TL3330AF260QG" SW_TL3330 2103.4,2155.53 r90 top
SW4 "B3U-3000P" SW_B3U-3000P 2141,2548 r180 top
"TI Logo 1" "Texas Instruments" TI_Stacked_Overlay_Medium 1045.38,1440.05 r180 bottom
TP1 "CMP-0078143-2" TESTPOINT 1348.79,2174.63 r180 top locked
TP2 "5015" Testpoint_Keystone_Miniature 2050.51,3848.13 r270 top
U1 "MSP432E401YTPDT" PDT0128A 589.56,3253.25 r90 top locked
U2 "LM4040B25IDBZR" DBZ0003A_N 1398.04,3052.32 r0 top locked
U3 "SN74LVC1T45DCKR" DCK0006A_N 964.47,3835.78 r180 top locked
U4 "TPD4S010DQAR" DQA0010A 292.91,3799.23 r270 top locked
U5 "SN74LVC1T45DCKR" DCK0006A_N 1259.15,3434.78 r180 top locked
U6 "CMP-0037789-2" DSG0008A 1562.11,3826.93 r0 top locked
U7 "SN74LVC1T45DCKR" DCK0006A_N 1259.15,3243.6 r180 top locked
U8 "BMA280" 12LGA 749.29,1422.19 r0 top locked
U9 "MX25R6435FM2IL0" SOP-8_200MIL 830.4,1829.88 r90 top locked
U10 "OPA4342EA/250" PW0014A_N 488.86,2310.14 r180 top locked
U11 "TMP116AIDRVR" DRV0006A 1068.39,1422.6 r90 top locked
Y1 "CMP-0004648-3" XTAL_ABM3 495.23,3768.32 r0 top locked
ZZ1 "These assemblies are ESD sensitive, ESD precautions shall be observed." AssemblyNote -1057.06,4806.27 r0 top
ZZ2 "These assemblies must be clean and free from flux and all contaminants. Use of no clean flux is not acceptable." AssemblyNote -1059.52,4730.66 r0 top
ZZ3 "These assemblies must comply with workmanship standards IPC-A-610 Class 2, unless otherwise specified." AssemblyNote -1059.08,4651.18 r0 top
ZZ4 "INDICATION FOR COMPONENTS D* (EXCEPT D3) ARE GIVEN AT THEIR CATHODE SIDE." AssemblyNote -1058.46,4570.97 r0 top
ZZ5 "This Assembly Note is for PCB labels only" AssemblyNoteLabel -1056.35,4495.94 r0 top
ZZ6 "Place a click-in Standoff (MAE-10, KangYang) in mounting hole #1 (0mil,4079mil) and mounting hole #2 (2100mil,4079mil) at the top of the board." AssemblyNote -1056.57,4423.83 r0 top
ZZ7 "Place a click-in Standoff (MAE-10, KangYang) in mounting hole #3 (0mil,0mil) and mounting hole #4 (2100mil,0mil) at the bottom of the board." AssemblyNote -1060.89,4341.9 r0 top

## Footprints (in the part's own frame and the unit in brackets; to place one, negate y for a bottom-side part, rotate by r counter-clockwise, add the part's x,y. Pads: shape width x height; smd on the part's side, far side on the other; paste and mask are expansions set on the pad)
3M_961102-6404-AR [mm] "Header, 2.54mm, 2x1, TH"
  rect 1.6x1.6 hole 1.1 mask+0.064: 1(-1.27,0)
  round 1.6 hole 1.1 mask+0.064: 2(1.27,0)
  silkscreen extent -2.52,-1.25 2.52,1.5, body extent -2.52,-1.25 2.52,1.25, height 8.5
12LGA [mm] "LGA, 12-Leads, Body 2x2mm, Pitch 0.5mm"
  rect 0.41x0.28 smd: 1(-0.815,0.75) 2(-0.815,0.25) 3(-0.815,-0.25) 4(-0.815,-0.75) 7(0.815,-0.75) 8(0.815,-0.25) 9(0.815,0.25) 10(0.815,0.75)
  rect 0.28x0.41 smd: 5(-0.25,-0.815) 6(0.25,-0.815) 11(0.25,0.815) 12(-0.25,0.815)
  silkscreen extent -1.3,0.7 -0.8,1.2, body extent -1,-1 1,1, height 1.01
19-217_R6C-AL1M2VY_3T_Red [mm] "SMD, 2-Leads, Body 1.6x0.8mm"
  rrect20% 0.5x0.9 smd: 1(-0.65,0) 2(0.65,0)
  body extent -0.85,-0.45 0.85,0.45, height 0.5
19-337_RGB [mm] "SMD, 6-Leads, Body 1.6x1.6mm"
  rect 0.55x0.4 smd: 1(-0.675,0.725) 3(-0.675,-0.725) 4(0.675,0.725) 6(0.675,-0.725)
  rect 0.7x0.5 smd: 2(-0.75,0) 5(0.75,0)
  silkscreen extent -1.2,0.6 -1.2,0.9, body extent -0.85,-0.85 0.85,0.85, height 0.35
0402 [mm] "0402 from SM-752 data"
  rect 0.8x0.6 smd: 1(-0.6,0) 2(0.6,0)
  silkscreen extent -1.22,-0.52 1.22,0.52, body extent -0.55,-0.3 0.55,0.3, height 0.6
0603 [mm] "0603 from SM-752 data"
  rect 1x0.95 smd: 1(-0.8,0) 2(0.8,0)
  silkscreen extent -1.52,-0.69 1.52,0.69, body extent -0.87,-0.47 0.87,0.47, height 1
0805 [mm] "0805 from SM-752 data"
  rect 1.3x1.5 smd: 1(-0.85,0) 2(0.85,0)
  silkscreen extent -1.72,-0.97 1.72,0.97, body extent -1.1,-0.72 1.1,0.72, height 1.45
0805_HV [mil] "0805 with 30mil clearance between pads"
  rect 50x63 smd: 1(-40,0) 2(40,0)
  silkscreen extent -74,-40 74,40, body extent -43,-29 43,29, height 57
1206_180 [mm] "1206_180"
  rect 1.1x1.6 smd: 1(-1.7,0) 2(1.7,0)
  body extent -1.75,-0.95 1.75,0.95, height 1.8
1206_180M [mm] "1206_180"
  rect 1.5x1.95 smd: 1(-1.55,0) 2(1.55,0)
  body extent -1.75,-0.95 1.75,0.95, height 1.8
AssemblyNote [mil] "Assembly Note"
AssemblyNoteLabel [mil] "Assembly Note for PCB Labels"
BoosterPack_40pin_J1J3 [mm] "Receptacle, 2.54mm, 10x2, TH"
  rrect6% 1.55x1.55 hole 1.02 mask+0.064: 1(1.27,11.43)
  round 1.55 hole 1.02 mask+0.064: 2(1.27,8.89) 3(1.27,6.35) 4(1.27,3.81) 5(1.27,1.27) 6(1.27,-1.27) 7(1.27,-3.81) 8(1.27,-6.35) 9(1.27,-8.89) 10(1.27,-11.43) 21(-1.27,11.43) 22(-1.27,8.89) 23(-1.27,6.35) 24(-1.27,3.81) 25(-1.27,1.27) 26(-1.27,-1.27) 27(-1.27,-3.81) 28(-1.27,-6.35) 29(-1.27,-8.89) 30(-1.27,-11.43)
  silkscreen extent -7.62,-12.95 7.62,12.95, body extent -2.48,-12.95 2.48,12.95, height 8.51
BoosterPack_40pin_J2J4 [mm] "Receptacle, 2.54mm, 10x2, TH"
  round 1.55 hole 1.02 mask+0.064: 11(-1.27,-11.43) 12(-1.27,-8.89) 13(-1.27,-6.35) 14(-1.27,-3.81) 15(-1.27,-1.27) 16(-1.27,1.27) 17(-1.27,3.81) 18(-1.27,6.35) 19(-1.27,8.89) 20(-1.27,11.43) 31(1.27,-11.43) 32(1.27,-8.89) 33(1.27,-6.35) 34(1.27,-3.81) 35(1.27,-1.27) 36(1.27,1.27) 37(1.27,3.81) 38(1.27,6.35) 39(1.27,8.89) 40(1.27,11.43)
  silkscreen extent -7.62,-12.95 2.48,12.95, body extent -2.48,-12.95 2.48,12.95, height 8.51
CE_Mark_5mm [mil] "Minimum text height for CE Mark"
  silkscreen extent -138,-98 138,98
CONN_PEC03SAAN [mm] "SULLINS"
  rect 1.5x1.5 hole 1.016 mask+0.064: 1(-2.54,0)
  round 1.5 hole 1.016 mask+0.064: 2(0,0) 3(2.54,0)
  silkscreen extent -3.81,-1.27 3.81,1.27, body extent -3.84,-1.3 3.84,1.3, height 8.38
DBZ0003A_N [mm] "SOT23, 3-Leads, Body 2.9x1.3mm, Pitch 0.95mm, Lead Span 2.4mm, IPC Medium Density"
  rrect17% 1x0.6 smd: 1(-1.2,0.95) 2(-1.2,-0.95) 3(1.2,0)
  silkscreen extent 0.2,-1.5 0.7,1.5, body extent -1.26,-1.46 1.26,1.46, height 0.98
DCK0006A_N [mm] "SOT23, 6-Leads, Body 2x1.3mm, Pitch 0.65mm, Lead Span 2.1mm, IPC Medium Density"
  rrect25% 0.85x0.4 smd: 1(-1.125,0.65) 2(-1.125,0) 3(-1.125,-0.65) 4(1.125,-0.65) 5(1.125,0) 6(1.125,0.65)
  silkscreen extent -1.5,-1.09 0.51,1.09, body extent -1.14,-1 1.14,1, height 0.95
DQA0010A [mm] "SON, 10-Leads, Body 1x2.5mm, Pitch 0.5mm, TI Recommended"
  rrect50% 0.565x0.2 smd: 1(-0.417,1) 2(-0.417,0.5) 4(-0.417,-0.5) 5(-0.417,-1) 6(0.417,-1) 7(0.417,-0.5) 9(0.417,0.5) 10(0.417,1)
  rrect28% 0.565x0.36 on Top Paste: 3(-0.417,0) 8(0.417,0)
  rrect25% 0.565x0.4 smd paste-0.2: 3(-0.417,0) 8(0.417,0)
  silkscreen extent -0.67,-1.45 0.55,1.45, body extent -0.55,-1.3 0.55,1.3, height 0.56
DRV0006A [mm] "SON, 6-Leads, Body 2x2mm, Pitch 0.65mm, Thermal Pad 1.6x1mm, TI Recommended"
  rrect33% 0.45x0.3 smd: 1(-0.975,0.65) 2(-0.975,0) 3(-0.975,-0.65) 4(0.975,-0.65) 5(0.975,0) 6(0.975,0.65)
  rrect14% 1x0.7 on Top Paste: 7(0,0.45) 7(0,-0.45)
  rrect10% 1x1.6 smd paste-0.5: 7(0,0)
  silkscreen extent -1.05,-1.2 1.05,1.2, body extent -1.05,-1.05 1.05,1.05, height 0.81
DSG0008A [mm] "SON, 8-Leads, Body 2x2mm, Pitch 0.5mm, Thermal Pad 1.6x0.9mm, TI Recommended"
  rrect40% 0.5x0.25 smd: 1(-0.95,0.75) 2(-0.95,0.25) 3(-0.95,-0.25) 4(-0.95,-0.75) 5(0.95,-0.75) 6(0.95,-0.25) 7(0.95,0.25) 8(0.95,0.75)
  rrect14% 0.9x0.7 on Top Paste: 9(0,-0.45) 9(0,0.45)
  rrect11% 0.9x1.6 smd paste-0.45: 9(0,0)
  silkscreen extent -1.07,-1.15 1.07,1.15, body extent -1,-1 1,1, height 0.77
ESD_Overlay_Medium [mil]
  silkscreen extent -127,-109 125,110
FCC_disclaimer [mil]
Fiducial10-20 [mm]
  round 1 smd mask+0.5: 1(0,0)
  TOP keep-out circle w1.178: c0,0 r0.5
KY_MAE-10 [mm] "Spacer Nylon Support"
  round 2.8 hole 3 unplated mask+0.102: ""(0,0)
  body extent -3.19,-2.75 3.19,2.75, height 10
Label_650x200 [mil] "Thermal Transfer Label"
  round 1 on Mech13: 0(0,0)
  silkscreen extent -325,-100 325,100, body extent -325,-100 325,100, height 1
LED_SML-LX0603GW [mm] "LUMEX OPTO"
  rect 0.8x0.8 smd: 1(-0.75,0) 2(0.75,0)
  silkscreen extent 1.4,-0.4 1.8,0.4, body extent -0.8,-0.4 0.8,0.4, height 0.6
Molex_1051640001 [mm] "Receptacle, USB 2.0, Micro B, 5 Pos, 0.65mm Pitch, R/A, SMT"
  rrect22% 0.45x1.38 smd: 1(1.3,4.11) 2(0.65,4.11) 3(0,4.11) 4(-0.65,4.11) 5(-1.3,4.11)
  rrect7% 1.475x2.1 smd: 6(-2.462,3.75) 11(2.462,3.75)
  rrect100% 1.4x2.1 hole 0.6 slot 1.3 at 90 deg mask+0.064: 7(-3.95,1.45) 10(3.95,1.45)
  rrect7% 1.375x1.9 smd: 8(-0.937,1.45) 9(0.937,1.45)
  silkscreen extent 1.2,5.1 1.4,5.4, body extent -4.1,-0.7 4.1,4.47, height 2.45
MON0063A [mm] "QFM"
  rrect22% 0.9x0.9 smd paste-0.05 mask-0.05: 1(-11.774,9.524) 2(-11.774,8.255) 3(-11.774,6.985) 4(-11.774,5.715) 5(-11.774,4.445) 6(-11.774,3.175) 7(-11.774,1.905) 8(-11.774,0.635) 9(-11.774,-0.635) 10(-11.774,-1.905) 11(-11.774,-3.175) 12(-11.774,-4.445) 13(-11.774,-5.715) 14(-11.774,-6.985) 15(-11.774,-8.255) 16(-11.774,-9.524) 17(-10.074,-9.524) 18(-8.804,-9.524) 19(-7.534,-9.524) 20(-6.264,-9.524) 21(-4.994,-9.524) 22(-3.724,-9.524) 23(-2.454,-9.524) 24(-1.184,-9.524) 25(0.086,-9.524) 26(1.356,-9.524) 27(2.626,-9.524) 28(4.326,-9.524) 29(4.326,-8.255) 30(4.326,-6.985) 31(4.326,-5.715) 32(4.326,-4.445) 33(4.326,-3.175) 34(4.326,-1.905) 35(4.326,-0.635) 36(4.326,0.635) 37(4.326,1.905) 38(4.326,3.175) 39(4.326,4.445) 40(4.326,5.715) 41(4.326,6.985) 42(4.326,8.255) 43(4.326,9.524) 44(2.626,9.524) 45(1.356,9.524) 46(0.086,9.524) 47(-1.184,9.524) 48(-2.454,9.524) 49(-3.724,9.524) 50(-4.994,9.524) 51(-6.264,9.524) 52(-7.534,9.524) 53(-8.804,9.524) 54(-10.074,9.524)
  rrect11% 0.89x0.89 on Top Paste: 55(-8.774,3.95) 55(-7.674,3.95) 56(-8.774,0.95) 56(-8.774,2.05) 56(-7.674,0.95) 56(-7.674,2.05) 57(-8.774,-2.05) 57(-8.774,-0.95) 57(-7.674,-2.05) 57(-7.674,-0.95) 58(-5.774,3.95) 58(-5.774,5.05) 58(-4.674,3.95) 58(-4.674,5.05) 59(-5.774,2.05) 59(-5.774,0.95) 59(-4.674,2.05) 59(-4.674,0.95) 60(-5.774,-0.95) 60(-5.774,-2.05) 60(-4.674,-0.95) 60(-4.674,-2.05) 61(-2.774,5.05) 61(-2.774,3.95) 61(-1.674,5.05) 61(-1.674,3.95) 62(-2.774,2.05) 62(-2.774,0.95) 62(-1.674,2.05) 62(-1.674,0.95) 63(-2.774,-0.95) 63(-2.774,-2.05) 63(-1.674,-0.95) 63(-1.674,-2.05)
  rrect5% 2x2 smd paste-1 mask-1: 55(-8.224,4.5)
  rrect5% 2x2 smd paste-1 mask+0: 56(-8.224,1.5) 57(-8.224,-1.5) 58(-5.224,4.5) 59(-5.224,1.5) 60(-5.224,-1.5) 61(-2.224,4.5) 62(-2.224,1.5) 63(-2.224,-1.5)
  TOP region: -9.274,-2.45 -9.274,5.45 -9.266,5.488 -9.245,5.521 -9.212,5.542 -9.174,5.55 -9.174,5.55 -1.274,5.55 -1.236,5.542 -1.203,5.521 -1.182,5.488 -1.174,5.45 -1.174,5.45 -1.174,-2.45 -1.182,-2.488 -1.203,-2.521 -1.236,-2.542 -1.274,-2.55 -1.274,-2.55 -9.174,-2.55 -9.212,-2.542 -9.245,-2.521 -9.266,-2.488 -9.274,-2.45
  silkscreen extent -12.75,-10.5 12.75,10.5, body extent -12.5,-10.25 12.5,10.25, height 2.32
PDT0128A [mm] "Thin QFP, 128-Leads, Body 14x14mm, Pitch 0.4mm"
  oval 1.4x0.2 smd: 1(-7.7,6.2) 2(-7.7,5.8) 3(-7.7,5.4) 4(-7.7,5) 5(-7.7,4.6) 6(-7.7,4.2) 7(-7.7,3.8) 8(-7.7,3.4) 9(-7.7,3) 10(-7.7,2.6) 11(-7.7,2.2) 12(-7.7,1.8) 13(-7.7,1.4) 14(-7.7,1) 15(-7.7,0.6) 16(-7.7,0.2) 17(-7.7,-0.2) 18(-7.7,-0.6) 19(-7.7,-1) 20(-7.7,-1.4) 21(-7.7,-1.8) 22(-7.7,-2.2) 23(-7.7,-2.6) 24(-7.7,-3) 25(-7.7,-3.4) 26(-7.7,-3.8) 27(-7.7,-4.2) 28(-7.7,-4.6) 29(-7.7,-5) 30(-7.7,-5.4) 31(-7.7,-5.8) 32(-7.7,-6.2) 65(7.7,-6.2) 66(7.7,-5.8) 67(7.7,-5.4) 68(7.7,-5) 69(7.7,-4.6) 70(7.7,-4.2) 71(7.7,-3.8) 72(7.7,-3.4) 73(7.7,-3) 74(7.7,-2.6) 75(7.7,-2.2) 76(7.7,-1.8) 77(7.7,-1.4) 78(7.7,-1) 79(7.7,-0.6) 80(7.7,-0.2) 81(7.7,0.2) 82(7.7,0.6) 83(7.7,1) 84(7.7,1.4) 85(7.7,1.8) 86(7.7,2.2) 87(7.7,2.6) 88(7.7,3) 89(7.7,3.4) 90(7.7,3.8) 91(7.7,4.2) 92(7.7,4.6) 93(7.7,5) 94(7.7,5.4) 95(7.7,5.8) 96(7.7,6.2)
  oval 0.2x1.4 smd: 33(-6.2,-7.7) 34(-5.8,-7.7) 35(-5.4,-7.7) 36(-5,-7.7) 37(-4.6,-7.7) 38(-4.2,-7.7) 39(-3.8,-7.7) 40(-3.4,-7.7) 41(-3,-7.7) 42(-2.6,-7.7) 43(-2.2,-7.7) 44(-1.8,-7.7) 45(-1.4,-7.7) 46(-1,-7.7) 47(-0.6,-7.7) 48(-0.2,-7.7) 49(0.2,-7.7) 50(0.6,-7.7) 51(1,-7.7) 52(1.4,-7.7) 53(1.8,-7.7) 54(2.2,-7.7) 55(2.6,-7.7) 56(3,-7.7) 57(3.4,-7.7) 58(3.8,-7.7) 59(4.2,-7.7) 60(4.6,-7.7) 61(5,-7.7) 62(5.4,-7.7) 63(5.8,-7.7) 64(6.2,-7.7) 97(6.2,7.7) 98(5.8,7.7) 99(5.4,7.7) 100(5,7.7) 101(4.6,7.7) 102(4.2,7.7) 103(3.8,7.7) 104(3.4,7.7) 105(3,7.7) 106(2.6,7.7) 107(2.2,7.7) 108(1.8,7.7) 109(1.4,7.7) 110(1,7.7) 111(0.6,7.7) 112(0.2,7.7) 113(-0.2,7.7) 114(-0.6,7.7) 115(-1,7.7) 116(-1.4,7.7) 117(-1.8,7.7) 118(-2.2,7.7) 119(-2.6,7.7) 120(-3,7.7) 121(-3.4,7.7) 122(-3.8,7.7) 123(-4.2,7.7) 124(-4.6,7.7) 125(-5,7.7) 126(-5.4,7.7) 127(-5.8,7.7) 128(-6.2,7.7)
  silkscreen extent -7.7,-6.3 6.3,6.99, body extent -8,-8 8,8, height 1.07
PW0014A_N [mm] "TSOP, 14-Leads, Body 5x4.4mm, Pitch 0.65mm, IPC Medium Density"
  oval 1.4x0.45 smd: 1(-2.95,1.95) 2(-2.95,1.3) 3(-2.95,0.65) 4(-2.95,0) 5(-2.95,-0.65) 6(-2.95,-1.3) 7(-2.95,-1.95) 8(2.95,-1.95) 9(2.95,-1.3) 10(2.95,-0.65) 11(2.95,0) 12(2.95,0.65) 13(2.95,1.3) 14(2.95,1.95)
  silkscreen extent -3.4,-2.55 1.85,2.55, body extent -3.21,-2.5 3.21,2.5, height 1
Samtec_FTSH-105-01-x-D-K [mm] "Header, 1.27 mm, 5x2, TH"
  rect 1.05x1.05 hole 0.71 mask+0.064: 1(-0.635,2.54)
  round 1.05 hole 0.71 mask+0.064: 2(0.635,2.54) 3(-0.635,1.27) 4(0.635,1.27) 5(-0.635,0) 6(0.635,0) 7(-0.635,-1.27) 8(0.635,-1.27) 9(-0.635,-2.54) 10(0.635,-2.54)
  silkscreen extent -2.54,-3.17 2.54,3.2, body extent -2.54,-3.17 2.54,3.1, height 5.73
Samtec_FTSH-107-01-x-DV [mm] "Header, 1.27mm, 7x2, SMT"
  rect 2.79x0.74 smd: 1(-2.035,3.81) 2(2.035,3.81) 3(-2.035,2.54) 4(2.035,2.54) 5(-2.035,1.27) 6(2.035,1.27) 7(-2.035,0) 8(2.035,0) 9(-2.035,-1.27) 10(2.035,-1.27) 11(-2.035,-2.54) 12(2.035,-2.54) 13(-2.035,-3.81) 14(2.035,-3.81)
  silkscreen extent -4.04,3.69 -3.79,3.94, body extent -2.94,-4.48 2.9,4.41, height 5.97
SML-31_Red [mm] "Rohm"
  rect 0.8x0.8 smd: 1(-0.825,0) 2(0.825,0)
  silkscreen extent -1.93,-0.76 1.1,0.76, body extent -0.85,-0.45 0.85,0.45, height 0.91
SNT-100-BK-G [mil] "Samtec STEP model"
  round 1 on Mech3: 0(0,0)
  body extent -100,-50 100,50, height 344
SOD-523F [mm] "COMCHIP"
  rect 0.6x0.8 smd paste-0.05: 1(-0.85,0) 2(0.85,0)
  silkscreen extent -1.92,-0.87 1.1,0.88, body extent -0.9,-0.5 0.9,0.5, height 0.85
SOP-8_200MIL [mm] "SOP, 8-Leads, Body 5.28x5.23mm, Pitch 1.27mm"
  rrect15% 1.7x0.65 smd: 1(-3.55,1.905) 2(-3.55,0.635) 3(-3.55,-0.635) 4(-3.55,-1.905) 5(3.55,-1.905) 6(3.55,-0.635) 7(3.55,0.635) 8(3.55,1.905)
  silkscreen extent -2.7,-2.65 2.7,2.9, body extent -2.7,-2.65 2.7,2.65, height 2.16
SOT-23 [mm] "SOT23, 3-Leads, Body 2.9x1.3mm, Pitch 0.95mm, Lead Span 2.5mm, IPC Medium Density"
  rrect50% 1x0.6 smd: 1(-1.2,0.95) 2(-1.2,-0.95) 3(1.2,0)
  silkscreen extent -1.62,-1.5 0.7,1.5, body extent -1.16,-1.45 1.21,1.45, height 1
SOT-363 [mm]
  rect 0.6x0.42 smd mask+0.051: 1(-0.95,0.65) 2(-0.95,0) 3(-0.95,-0.65) 4(0.95,-0.65) 5(0.95,0) 6(0.95,0.65)
  silkscreen extent -0.38,-1.02 0.38,1.02, body extent -1.1,-1.1 1.1,1.1, height 1.12
SSOT-3 [mm] "SuperSOT-3"
  rect 1x1.4 smd: 1(-0.95,-1.1) 2(0.95,-1.1) 3(0,1.1)
  silkscreen extent -1.53,-0.05 1.5,0.77, body extent -1.52,-0.76 1.52,0.76, height 1.12
SW_B3U-3000P [mm] "SMD, 2-Leads, Body 3x2.5mm"
  rrect12% 1.7x0.8 smd: 1(0,1.7) 2(0,-1.7)
  silkscreen extent -1.95,-1.5 1.25,1.5, body extent -1.95,-2 1.25,2, height 1.2
SW_TL3330 [mm] "SMD, 4-Leads, Body 7.8x3.5mm"
  rect 0.9x1.27 smd: 1(-2.1,0.885) 2(2.1,0.885)
  rect 1.45x0.8 smd: 3(-3.375,-1) 4(3.375,-1)
  silkscreen extent -3.45,-1.25 3.45,1.25, body extent -3.9,-2.25 3.9,1.35, height 3.5
Tag_TC2050-NL [mil] "Footprint for Tag-Connect TC2050 No-Legs cables"
  round 31 smd paste-15.75: 1(-25,100) 2(-25,50) 3(-25,0) 4(-25,-50) 5(-25,-100) 6(25,-100) 7(25,-50) 8(25,0) 9(25,50) 10(25,100)
  round 39 hole 39 unplated mask+5: MH1(0,150) MH2(-40,-150) MH3(40,-150)
  silkscreen extent -105,-200 75,200
TESTPOINT [mil]
  round 80 hole 37.99 mask+2.5: 1(0,0)
Testpoint_Keystone_Miniature [mil] "Miniature SMT test point"
  rect 135x70 smd: 1(0,0)
  silkscreen extent -78,-46 78,45, body extent -52,-20 52,20, height 61
TI_Stacked_Overlay_Medium [mil]
  silkscreen extent -576,-136 576,135
TI_Symbol_Overlay_Medium [mil]
  silkscreen extent -125,-122 124,120
WEEE_Minimum [mil] "WEEElie bin"
  silkscreen extent -95,-172 99,104
WL-SMCW_YELLOW [mm] "WURTH"
  rect 0.8x0.8 smd: 1(-0.8,0) 2(0.8,0)
  silkscreen extent -1.9,-0.8 1.2,0.8, body extent -0.85,-0.45 0.85,0.45, height 0.8
WURTH_61300211121 [mm] "Header, 2.54mm, 2x1, TH"
  rect 1.65x1.65 hole 1.15 mask+0.064: 1(-1.27,0)
  round 1.65 hole 1.15 mask+0.064: 2(1.27,0)
  silkscreen extent -2.54,-1.27 2.54,1.27, body extent -2.54,-1.27 2.54,1.27, height 8.54
WURTH_61300311121 [mm] "Header, 2.54mm, 3x1, TH"
  rect 1.65x1.65 hole 1.15 mask+0.064: 1(-2.54,0)
  round 1.65 hole 1.15 mask+0.064: 2(0,0) 3(2.54,0)
  silkscreen extent -3.81,-1.27 3.81,1.27, body extent -3.81,-1.27 3.81,1.27, height 8.54
Wurth_61300621121 [mm] "Header, 2.54mm, 3x2, TH"
  rect 1.6x1.6 hole 1.1 mask+0.064: 1(-1.27,2.54)
  round 1.6 hole 1.1 mask+0.064: 2(1.27,2.54) 3(-1.27,0) 4(1.27,0) 5(-1.27,-2.54) 6(1.27,-2.54)
  silkscreen extent -2.8,-3.82 2.54,3.8, body extent -2.54,-3.82 2.54,3.8, height 7.27
WURTH_61301021121 [mm] "Header, 2.54mm, 5x2, TH"
  rrect25% 1.65x1.65 hole 1.15 mask+0.064: 1(-5.08,-1.27)
  round 1.65 hole 1.15 mask+0.064: 2(-5.08,1.27) 3(-2.54,-1.27) 4(-2.54,1.27) 5(0,-1.27) 6(0,1.27) 7(2.54,-1.27) 8(2.54,1.27) 9(5.08,-1.27) 10(5.08,1.27)
  silkscreen extent -6.35,-2.54 6.35,2.54, body extent -6.35,-2.54 6.35,2.54, height 8.54
XTAL_ABM3 [mm] "Abracon recommended land pattern 12.28.10"
  rect 1.9x2.4 smd: 1(-2.05,0) 2(2.05,0)
  silkscreen extent -2.67,-1.78 2.67,1.78, body extent -2.6,-1.7 2.6,1.7, height 1.3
